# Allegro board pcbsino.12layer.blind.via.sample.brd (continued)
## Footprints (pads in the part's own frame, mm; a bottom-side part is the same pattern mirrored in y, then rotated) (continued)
0805
  rect 1.143x1.27 smd: 1(-0.889,0) 2(0.889,0)
1210
  rect 1.6x2.667 smd: 1(-1.397,0) 2(1.397,0)
FILT-NFM21PC
  rect 0.6x0.8 smd: 1(-1,0) 3(1,0)
  rect 0.6x1.3 smd: 2(0,0)
IND_IHLP1616AB
  rect 1.651x2.413 smd: 1(-1.651,0) 2(1.651,0)
LED_0603
  rect 0.889x0.813 smd: 1(-0.762,0) 2(0.762,0)
NFBGA_ZWS_169
  round 0.4 smd: A1(-4.8,4.8) A2(-4,4.8) A3(-3.2,4.8) A4(-2.4,4.8) A5(-1.6,4.8) A6(-0.8,4.8) A7(0,4.8) A8(0.8,4.8) A9(1.6,4.8) A10(2.4,4.8) A11(3.2,4.8) A12(4,4.8) A13(4.8,4.8) B1(-4.8,4) B2(-4,4) B3(-3.2,4) B4(-2.4,4) B5(-1.6,4) B6(-0.8,4) B7(0,4) B8(0.8,4) B9(1.6,4) B10(2.4,4) B11(3.2,4) B12(4,4) B13(4.8,4) C1(-4.8,3.2) C2(-4,3.2) C3(-3.2,3.2) C4(-2.4,3.2) C5(-1.6,3.2) C6(-0.8,3.2) C7(0,3.2) C8(0.8,3.2) C9(1.6,3.2) C10(2.4,3.2) C11(3.2,3.2) C12(4,3.2) C13(4.8,3.2) D1(-4.8,2.4) D2(-4,2.4) D3(-3.2,2.4) D4(-2.4,2.4) D5(-1.6,2.4) D6(-0.8,2.4) D7(0,2.4) D8(0.8,2.4) D9(1.6,2.4) D10(2.4,2.4) D11(3.2,2.4) D12(4,2.4) D13(4.8,2.4) E1(-4.8,1.6) E2(-4,1.6) E3(-3.2,1.6) E4(-2.4,1.6) E5(-1.6,1.6) E6(-0.8,1.6) E7(0,1.6) E8(0.8,1.6) E9(1.6,1.6) E10(2.4,1.6) E11(3.2,1.6) E12(4,1.6) E13(4.8,1.6) F1(-4.8,0.8) F2(-4,0.8) F3(-3.2,0.8) F4(-2.4,0.8) F5(-1.6,0.8) F6(-0.8,0.8) F7(0,0.8) F8(0.8,0.8) F9(1.6,0.8) F10(2.4,0.8) F11(3.2,0.8) F12(4,0.8) F13(4.8,0.8) G1(-4.8,0) G2(-4,0) G3(-3.2,0) G4(-2.4,0) G5(-1.6,0) G6(-0.8,0) G7(0,0) G8(0.8,0) G9(1.6,0) G10(2.4,0) G11(3.2,0) G12(4,0) G13(4.8,0) H1(-4.8,-0.8) H2(-4,-0.8) H3(-3.2,-0.8) H4(-2.4,-0.8) H5(-1.6,-0.8) H6(-0.8,-0.8) H7(0,-0.8) H8(0.8,-0.8) H9(1.6,-0.8) H10(2.4,-0.8) H11(3.2,-0.8) H12(4,-0.8) H13(4.8,-0.8) J1(-4.8,-1.6) J2(-4,-1.6) J3(-3.2,-1.6) J4(-2.4,-1.6) J5(-1.6,-1.6) J6(-0.8,-1.6) J7(0,-1.6) J8(0.8,-1.6) J9(1.6,-1.6) J10(2.4,-1.6) J11(3.2,-1.6) J12(4,-1.6) J13(4.8,-1.6) K1(-4.8,-2.4) K2(-4,-2.4) K3(-3.2,-2.4) K4(-2.4,-2.4) K5(-1.6,-2.4) K6(-0.8,-2.4) K7(0,-2.4) K8(0.8,-2.4) K9(1.6,-2.4) K10(2.4,-2.4) K11(3.2,-2.4) K12(4,-2.4) K13(4.8,-2.4) L1(-4.8,-3.2) L2(-4,-3.2) L3(-3.2,-3.2) L4(-2.4,-3.2) L5(-1.6,-3.2) L6(-0.8,-3.2) L7(0,-3.2) L8(0.8,-3.2) L9(1.6,-3.2) L10(2.4,-3.2) L11(3.2,-3.2) L12(4,-3.2) L13(4.8,-3.2) M1(-4.8,-4) M2(-4,-4) M3(-3.2,-4) M4(-2.4,-4) M5(-1.6,-4) M6(-0.8,-4) M7(0,-4) M8(0.8,-4) M9(1.6,-4) M10(2.4,-4) M11(3.2,-4) M12(4,-4) M13(4.8,-4) N1(-4.8,-4.8) N2(-4,-4.8) N3(-3.2,-4.8) N4(-2.4,-4.8) N5(-1.6,-4.8) N6(-0.8,-4.8) N7(0,-4.8) N8(0.8,-4.8) N9(1.6,-4.8) N10(2.4,-4.8) N11(3.2,-4.8) N12(4,-4.8) N13(4.8,-4.8)
PLLD1_27-20R
  round 1 hole 0.7: 1(-5.715,-0.635) 2(-5.715,0.635) 3(-4.445,-0.635) 4(-4.445,0.635) 5(-3.175,-0.635) 6(-3.175,0.635) 7(-1.905,-0.635) 8(-1.905,0.635) 9(-0.635,-0.635) 10(-0.635,0.635) 11(0.635,-0.635) 12(0.635,0.635) 13(1.905,-0.635) 14(1.905,0.635) 15(3.175,-0.635) 16(3.175,0.635) 17(4.445,-0.635) 18(4.445,0.635) 19(5.715,-0.635) 20(5.715,0.635)
QFN48
  oval 0.9x0.22 smd: 1(-2.95,2.2) 2(-2.95,1.8) 3(-2.95,1.4) 4(-2.95,1) 5(-2.95,0.6) 6(-2.95,0.2) 7(-2.95,-0.2) 8(-2.95,-0.6) 9(-2.95,-1) 10(-2.95,-1.4) 11(-2.95,-1.8) 12(-2.95,-2.2) 25(2.95,-2.2) 26(2.95,-1.8) 27(2.95,-1.4) 28(2.95,-1) 29(2.95,-0.6) 30(2.95,-0.2) 31(2.95,0.2) 32(2.95,0.6) 33(2.95,1) 34(2.95,1.4) 35(2.95,1.8) 36(2.95,2.2)
  oval 0.22x0.9 smd: 13(-2.2,-2.95) 14(-1.8,-2.95) 15(-1.4,-2.95) 16(-1,-2.95) 17(-0.6,-2.95) 18(-0.2,-2.95) 19(0.2,-2.95) 20(0.6,-2.95) 21(1,-2.95) 22(1.4,-2.95) 23(1.8,-2.95) 24(2.2,-2.95) 37(2.2,2.95) 38(1.8,2.95) 39(1.4,2.95) 40(1,2.95) 41(0.6,2.95) 42(0.2,2.95) 43(-0.2,2.95) 44(-0.6,2.95) 45(-1,2.95) 46(-1.4,2.95) 47(-1.8,2.95) 48(-2.2,2.95)
  rect 4.3x4.3 smd: 49(0,0)
RV-3129-C3
  rect 0.8x0.5 smd: 1(-1.15,1.6) 2(-1.15,0.8) 3(-1.15,0) 4(-1.15,-0.8) 5(-1.15,-1.6) 6(1.15,-1.6) 7(1.15,-0.8) 8(1.15,0) 9(1.15,0.8) 10(1.15,1.6)
SC-70-6
  rect 0.4x0.7 smd: 1(-0.65,-0.992) 2(0,-0.992) 3(0.65,-0.992) 4(0.65,0.992) 5(0,0.992) 6(-0.65,0.992)
SODIMM-204
  rect 0.45x2.5 smd: 1(0,0) 2(0,0) 3(0.6,0) 4(0.6,0) 5(1.2,0) 6(1.2,0) 7(1.8,0) 8(1.8,0) 9(2.4,0) 10(2.4,0) 11(3,0) 12(3,0) 13(3.6,0) 14(3.6,0) 15(4.2,0) 16(4.2,0) 17(4.8,0) 18(4.8,0) 19(5.4,0) 20(5.4,0) 21(6,0) 22(6,0) 23(6.6,0) 24(6.6,0) 25(7.2,0) 26(7.2,0) 27(7.8,0) 28(7.8,0) 29(8.4,0) 30(8.4,0) 31(9,0) 32(9,0) 33(9.6,0) 34(9.6,0) 35(10.2,0) 36(10.2,0) 37(10.8,0) 38(10.8,0) 39(11.4,0) 40(11.4,0) 41(12,0) 42(12,0) 43(12.6,0) 44(12.6,0) 45(13.2,0) 46(13.2,0) 47(13.8,0) 48(13.8,0) 49(14.4,0) 50(14.4,0) 51(15,0) 52(15,0) 53(15.6,0) 54(15.6,0) 55(16.2,0) 56(16.2,0) 57(16.8,0) 58(16.8,0) 59(17.4,0) 60(17.4,0) 61(18,0) 62(18,0) 63(18.6,0) 64(18.6,0) 65(19.2,0) 66(19.2,0) 67(19.8,0) 68(19.8,0) 69(20.4,0) 70(20.4,0) 71(21,0) 72(21,0) 73(24,0) 74(24,0) 75(24.6,0) 76(24.6,0) 77(25.2,0) 78(25.2,0) 79(25.8,0) 80(25.8,0) 81(26.4,0) 82(26.4,0) 83(27,0) 84(27,0) 85(27.6,0) 86(27.6,0) 87(28.2,0) 88(28.2,0) 89(28.8,0) 90(28.8,0) 91(29.4,0) 92(29.4,0) 93(30,0) 94(30,0) 95(30.6,0) 96(30.6,0) 97(31.2,0) 98(31.2,0) 99(31.8,0) 100(31.8,0) 101(32.4,0) 102(32.4,0) 103(33,0) 104(33,0) 105(33.6,0) 106(33.6,0) 107(34.2,0) 108(34.2,0) 109(34.8,0) 110(34.8,0) 111(35.4,0) 112(35.4,0) 113(36,0) 114(36,0) 115(36.6,0) 116(36.6,0) 117(37.2,0) 118(37.2,0) 119(37.8,0) 120(37.8,0) 121(38.4,0) 122(38.4,0) 123(39,0) 124(39,0) 125(39.6,0) 126(39.6,0) 127(40.2,0) 128(40.2,0) 129(40.8,0) 130(40.8,0) 131(41.4,0) 132(41.4,0) 133(42,0) 134(42,0) 135(42.6,0) 136(42.6,0) 137(43.2,0) 138(43.2,0) 139(43.8,0) 140(43.8,0) 141(44.4,0) 142(44.4,0) 143(45,0) 144(45,0) 145(45.6,0) 146(45.6,0) 147(46.2,0) 148(46.2,0) 149(46.8,0) 150(46.8,0) 151(47.4,0) 152(47.4,0) 153(48,0) 154(48,0) 155(48.6,0) 156(48.6,0) 157(49.2,0) 158(49.2,0) 159(49.8,0) 160(49.8,0) 161(50.4,0) 162(50.4,0) 163(51,0) 164(51,0) 165(51.6,0) 166(51.6,0) 167(52.2,0) 168(52.2,0) 169(52.8,0) 170(52.8,0) 171(53.4,0) 172(53.4,0) 173(54,0) 174(54,0) 175(54.6,0) 176(54.6,0) 177(55.2,0) 178(55.2,0) 179(55.8,0) 180(55.8,0) 181(56.4,0) 182(56.4,0) 183(57,0) 184(57,0) 185(57.6,0) 186(57.6,0) 187(58.2,0) 188(58.2,0) 189(58.8,0) 190(58.8,0) 191(59.4,0) 192(59.4,0) 193(60,0) 194(60,0) 195(60.6,0) 196(60.6,0) 197(61.2,0) 198(61.2,0) 199(61.8,0) 200(61.8,0) 201(62.4,0) 202(62.4,0) 203(63,0) 204(63,0)
SOT23
  rect 0.991x0.991 smd: 1(-0.965,-1.181) 2(0.965,-1.181)
  rect 0.991x1.2 smd: 3(0,1.081)
SOT23-3L
  rect 1.016x1.016 smd: 1(-1.016,-1.105) 2(1.016,-1.105) 3(0,1.105)
SOT323
  rect 0.5x0.6 smd: D(0,0.95) G(-0.65,-0.95) S(0.65,-0.95)
SOT-23-5
  rect 0.61x1.321 smd: 1(-0.95,-1.2) 2(0,-1.2) 3(0.95,-1.2) 4(0.95,1.2) 5(-0.95,1.2)
SOT-23-6
  rect 0.61x1.524 smd: 1(-0.95,-1.2) 2(0,-1.2) 3(0.95,-1.2) 4(0.95,1.2) 5(0,1.2) 6(-0.95,1.2)
SRN3015
  rect 2.7x1 smd: 1(0,1.1) 2(0,-1.1)
TP_SMD1MMCIRCLE
  round 1.021 smd: 1(0,0)
unnamed
  round 1.016 smd: 1(0,0)
XTAL4_3P2X2P5_SMD
  rect 1.397x1.143 smd: 1(-1.1,-0.8) 2(1.1,-0.8) 3(1.1,0.8) 4(-1.1,0.8)

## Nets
GND: C1.1 C2.2 C3.1 C4.2 C5.2 C6.2 C7.2 C8.1 C9.2 C10.2 C11.2 C12.2 C13.2 C14.2 C15.2 C16.2 C17.1 C18.2 C19.2 C20.2 C21.2 C22.2 C23.2 C24.2 C25.2 C26.2 C27.2 C28.2 C29.2 C30.2 C31.1 C32.2 C33.2 C34.2 C35.1 C36.1 C37.2 C38.2 C39.2 C40.1 C41.1 C42.2 C43.1 C44.1 C45.2 C46.1 C47.2 C48.1 C49.1 C50.1 C51.1 C52.2 C53.2 C54.2 C55.2 C56.2 C57.2 C58.2 C59.2 C60.2 C61.2 C62.2 C63.2 C64.2 C65.2 C69.2 C70.2 C71.2 C72.2 C76.2 C77.2 C78.2 C79.2 C80.2 C81.1 C82.1 C83.1 C84.1 C85.1 C86.2 C87.1 C88.1 C89.1 C90.1 C91.1 C92.2 C93.2 C94.2 C95.2 C96.2 C97.2 C98.2 C99.2 C100.2 C101.2 C102.2 C106.2 C107.2 C108.2 C109.2 C113.2 C114.2 C115.2 C116.2 C117.2 C118.1 C119.1 C120.1 C121.1 C122.1 C123.2 C124.1 C125.1 C126.1 C127.1 C128.1 C129.2 C130.2 C131.2 C132.2 C133.2 C134.2 C135.2 C136.2 C137.2 C138.2 C139.1 C140.1 C141.1 C142.1 C143.1 C144.2 C145.2 C146.1 C147.1 C148.1 C149.1 C150.1 C151.1 C152.2 C153.2 C154.2 C155.2 C156.2 C157.1 C158.2 C159.2 C160.2 C161.2 C162.2 C163.2 C164.2 C177.2 C178.1 C179.1 C180.2 C181.2 C182.2 C183.2 C184.2 C185.2 C186.2 C187.2 C188.2 C189.2 C190.2 C191.2 C192.2 C193.2 C194.2 C195.2 C196.2 C197.2 C198.2 C199.2 C200.2 C201.2 C202.2 C203.2 C204.2 C205.2 C206.2 C207.2 C208.2 C209.2 C210.2 C211.2 C212.2 C213.2 C214.2 C215.2 C216.2 C217.2 C218.2 C219.2 C220.2 C221.2 C222.2 C223.2 C224.2 C225.2 C226.2 C227.2 C228.2 C229.2 C230.2 C231.2 C232.2 C233.2 C234.2 C235.2 C236.2 C237.2 C238.2 C239.2 C240.2 C241.2 C242.2 C243.2 C244.2 C245.2 C246.2 C247.2 C248.2 C249.2 C250.2 C251.2 C252.2 C253.2 C254.2 C255.2 C256.2 C257.2 C258.2 C259.2 C260.2 C261.2 C262.2 C263.2 C264.2 C265.2 C266.2 C267.2 C268.2 C269.2 C270.2 C271.2 C272.2 C273.2 C274.2 C275.2 C276.2 C277.2 C278.2 C279.2 C280.2 C281.2 C282.2 C283.2 C284.2 C285.2 C286.2 C287.2 C288.2 C289.2 C290.2 C291.2 C292.2 C293.2 C294.2 C295.2 C296.2 C297.2 C298.2 C299.2 C300.2 C301.2 C302.2 C303.2 C304.2 C305.2 C306.2 C307.2 C308.2 C309.2 C310.2 C311.2 C312.2 C313.2 C314.2 C315.2 C316.2 C317.2 C318.2 C319.1 C320.2 C321.1 C322.2 C323.1 C324.2 C325.1 C326.2 C327.1 C328.2 C329.1 C330.2 C331.1 C332.2 C333.1 D1.1(C) L22.2(GND) L23.2(GND) L24.2(GND) MH1.1(TP) MH2.1(TP) MH3.1(TP) MH4.1(TP) MH5.1(TP) MH6.1(TP) P1.4(TDIS) P1.8(GND.1) P1.10(GND.2) P1.12(GND.3) P1.16(GND.4) P1.20(GND.5) Q3.S(SOURCE) Q4.S(SOURCE) Q5.S(SOURCE) Q6.S(SOURCE) Q7.S(SOURCE) Q8.S(SOURCE) R7.1 R22.1 R26.1 R29.2 R31.2 R34.2 R35.1 R37.1 R38.1 R39.1 R40.1 R42.1 R43.2 R46.2 R49.2 R52.2 R59.2 R60.2 R61.2 R62.2 R64.2 R95.2 R96.2 R97.2 R98.2 R99.1 R128.2 R129.2 R130.2 R131.2 R157.2 R158.2 R159.2 R160.1 R162.1 R183.2 R184.2 R191.2 R196.2 R198.2 R200.2 R202.2 R204.2 R206.2 R208.2 R214.2 R217.2 R219.2 R221.2 R223.2 R225.2 R231.2 R233.2 R236.2 R237.1 R238.1 R239.1 R272.1 R273.1 R274.1 R278.1 R280.1 R281.1 R282.1 R283.1 R285.1 R287.1 R301.1 R302.1 R303.1 R307.1 R309.1 R310.1 R311.1 R312.1 R314.1 R316.1 R318.2 R326.2 U1.2(GND) U2.4(PGND) U2.8(GND) U2.11(PWRPAD) U3.A1(SUB_GND_A1) U3.A4(REFGND1) U3.A7(GNDANA) U3.A13(SUB_GND_A13) U3.B2(GPADC_IN0) U3.B8(SYNC_TO_EXCLOCK) U3.B10(SUB_GND_B10) U3.B11(SUB_GND_B11) U3.C2(GPADC_IN1) U3.C3(GPADC_IN2) U3.C12(SMPS12_FBK_GND) U3.D4(SMPS7_GND_1) U3.D5(SMPS7_GND_2) U3.D6(SUB_GND_D6) U3.D7(SUB_GND_D7) U3.D10(SMPS1_GND_1) U3.E4(SMPS7_GND_3) U3.E7(VAC/ACOK) U3.E8(SUB_GND_E8) U3.E9(SMPS1_GND_2) U3.E10(SMPS1_GND_3) U3.F4(SMPS4_GND_1) U3.F5(AGND.1) U3.F6(SUB_GND_F6) U3.F7(SUB_GND_F7) U3.F9(SMPS2_GND_1) U3.F10(SMPS2_GND_2) U3.G4(SMPS4_GND_2) U3.G5(SMPS4_GND_3) U3.G7(SUB_GND_G7) U3.G10(SMPS2_GND_3) U3.H4(SMPS5_GND_1) U3.H5(SMPS5_GND_2) U3.H6(SUB_GND_H6) U3.H7(SUB_GND_H7) U3.H10(SMPS3_GND_1) U3.J4(SMPS5_GND_3) U3.J6(SUB_GND_J6) U3.J9(SMPS3_GND_2) U3.J10(SMPS3_GND_3) U3.K3(SMPS45_FDBK_GND) U3.L5(SMPS6_GND) U3.L6(SMPS6_GND_1) U3.L7(SMPS9_GND) U3.L8(SMPS9_GND_1) U3.L9(SMPS8_GND_1) U3.L10(SMPS8_GND) U3.M1(SUB_GND_M1) U3.M2(SUB_GND_M2) U3.M12(GND_DIG) U3.M13(AGND.2) U3.N1(SUB_GND_N1) U3.N2(VIO_GND) U3.N13(SUB_GND_N13) U4.3(GND) U5.3(GND) U6.A1(VSS.9) U6.A2(VSS.11) U6.A6(VSS.15) U6.A14(VSS.41) U6.A23(VSS.68) U6.A28(VSS.79) U6.AA8(VSS.17) U6.AA9(VSS.19) U6.AA10(VSS.14) U6.AA11(VSSA_USB.2) U6.AA14(VSS.48) U6.AA15(VSS.51) U6.AA20(VSS.61) U6.AB11(VSSA_USB.1) U6.AB14(VSS.40) U6.AB20(VSS.60) U6.AC14(VSSA_OSC1) U6.AD1(VSS.3) U6.AD10(VSSA_USB3) U6.AD13(VSSA_PCIE.1) U6.AD19(VSSA_HDMI.2) U6.AD24(VSS.70) U6.AE10(VSSA_SATA) U6.AE13(VSSA_PCIE.2) U6.AE19(VSSA_HDMI.1) U6.AF15(VSSA_OSC0) U6.AG1(VSS.2) U6.AH1(VSS.1) U6.AH2(VSS.10) U6.AH8(VSS.53) U6.AH20(VSS.52) U6.AH28(VSS.75) U6.B1(VSS.8) U6.D13(VSS.39) U6.D19(VSS.59) U6.E13(VSS.38) U6.E19(VSS.58) U6.F1(VSS.7) U6.F7(VSS.54) U6.G7(VSS.57) U6.G8(VSS.65) U6.G9(VSS.66) U6.H12(VSS.33) U6.J12(VSS.32) U6.J15(VSS.XX) U6.J28(VSS.78) U6.K1(VSS.6) U6.K4(VSS.12) U6.K5(VSS.13) U6.K15(VSS.28) U6.K24(VSS.55) U6.K25(VSS.56) U6.L13(VSS.37) U6.L14(VSS.46) U6.M19(VSS.69) U6.N14(VSS.X5) U6.N15(VSS.16) U6.N19(VSS.18) U6.N24(VSS.72) U6.N25(VSS.74) U6.P28(VSS.77) U6.R1(VSS.5) U6.R12(VSS.29) U6.R13(VSS.X6) U6.R15(VSS.43) U6.R21(VSS.64) U6.T10(VSS.21) U6.T11(VSS.26) U6.T12(VSS.23) U6.T14(VSS.X7) U6.T15(VSS.42) U6.T17(VSS.47) U6.T18(VSS.24) U6.T21(VSS.27) U6.U14(VSSA_VIDEO) U6.U15(VSS.X8) U6.U17(VSS.X9) U6.U20(VSS.62) U6.U21(VSS.63) U6.V15(VSS.30) U6.V17(VSS.X10) U6.W1(VSS.4) U6.W15(VSS.36) U6.W24(VSS.71) U6.W25(VSS.73) U6.W28(VSS.76) U7.3(GND) U8.A9(VSS.1) U8.B1(VSSQ.1) U8.B3(VSS.2) U8.B9(VSSQ.2) U8.D1(VSSQ.3) U8.D8(VSSQ.4) U8.E1(VSS.3) U8.E2(VSSQ.5) U8.E8(VSSQ.6) U8.F9(VSSQ.7) U8.G1(VSSQ.8) U8.G8(VSS.4) U8.G9(VSSQ.9) U8.J2(VSSDL) U8.J8(VSS.5) U8.M1(VSS.6) U8.M9(VSS.7) U8.P1(VSS.8) U8.P9(VSS.9) U8.T1(VSS.10) U8.T9(VSS.11) U9.A9(VSS.1) U9.B1(VSSQ.1) U9.B3(VSS.2) U9.B9(VSSQ.2) U9.D1(VSSQ.3) U9.D8(VSSQ.4) U9.E1(VSS.3) U9.E2(VSSQ.5) U9.E8(VSSQ.6) U9.F9(VSSQ.7) U9.G1(VSSQ.8) U9.G8(VSS.4) U9.G9(VSSQ.9) U9.J2(VSSDL) U9.J8(VSS.5) U9.M1(VSS.6) U9.M9(VSS.7) U9.P1(VSS.8) U9.P9(VSS.9) U9.T1(VSS.10) U9.T9(VSS.11) U10.A9(VSS.1) U10.B1(VSSQ.1) U10.B3(VSS.2) U10.B9(VSSQ.2) U10.D1(VSSQ.3) U10.D8(VSSQ.4) U10.E1(VSS.3) U10.E2(VSSQ.5) U10.E8(VSSQ.6) U10.F9(VSSQ.7) U10.G1(VSSQ.8) U10.G8(VSS.4) U10.G9(VSSQ.9) U10.J2(VSSDL) U10.J8(VSS.5) U10.M1(VSS.6) U10.M9(VSS.7) U10.P1(VSS.8) U10.P9(VSS.9) U10.T1(VSS.10) U10.T9(VSS.11) U11.A9(VSS.1) U11.B1(VSSQ.1) U11.B3(VSS.2) U11.B9(VSSQ.2) U11.D1(VSSQ.3) U11.D8(VSSQ.4) U11.E1(VSS.3) U11.E2(VSSQ.5) U11.E8(VSSQ.6) U11.F9(VSSQ.7) U11.G1(VSSQ.8) U11.G8(VSS.4) U11.G9(VSSQ.9) U11.J2(VSSDL) U11.J8(VSS.5) U11.M1(VSS.6) U11.M9(VSS.7) U11.P1(VSS.8) U11.P9(VSS.9) U11.T1(VSS.10) U11.T9(VSS.11) U12.A6(VSS1) U12.C4(VSSQ1) U12.E7(VSS2) U12.G5(VSS3) U12.H10(VSS4) U12.J5(VSS5) U12.K8(VSS6) U12.N2(VSSQ2) U12.N5(VSSQ3) U12.P4(VSSQ4) U12.P6(VSSQ5) U13.6(VSS) U14.2(GND) U15.4(GND) U16.4(VSS) U17.49(EGND) U18.3(GND) U19.49(EGND) U20.3(GND) XP1.1(GND17) XP1.19(GND18) XP1.37(GND19) XP1.55(GND20) XP1.71(GND21) XP1.87(GND) XP1.105(GND8) XP1.123(GND9) XP1.141(GND10) XP1.159(GND11) XP1.177(GND12) XP1.195(AUDIO_GND) Y1.2(NC0) Y1.4(NC1) Y2.2(NC0) Y2.4(NC1) Y3.2(NC0) Y3.4(NC1) Y4.2(NC0) Y4.4(NC1) Y5.2(NC0) Y5.4(NC1)
SODIMM_VIN5A_CLK0/VIN2B_HSYNC1: U6.AC5(EHRPWM2A) XP1.49(VIN5A_CLK0;GPIO6_10;I2C3_SDA;VI)
SODIMM_VIN5A_D0/VIN2B_D0: U6.AD6(MMC3_DAT5) XP1.163(VIN5A_D0;GPIO1_23;MMC3_DAT5;SPI)
SODIMM_VIN5A_D1/VIN2B_D1: U6.AC8(MMC3_DAT4) XP1.202(VIN5A_D1;PER_PWREN;GPIO1_22;MMC)
SODIMM_VIN5A_D2/VIN2B_D2: U6.AC3(MMC3_DAT3) XP1.52(VIN5A_D2;GPIO7_2;MMC3_DAT3;SPI3)
SODIMM_VIN5A_D3/VIN2B_D3: U6.AC9(MMC3_DAT2) XP1.58(VIN5A_D3;GPIO7_1;MMC3_DAT2;SPI3)
SODIMM_VIN5A_D4/VIN2B_D4: U6.AC6(MMC3_DAT1) XP1.65(VIN5A_D4;GPIO7_0;MMC3_DAT1;SPI3)
SODIMM_VIN5A_D5/VIN2B_D5: U6.AC7(MMC3_DAT0) XP1.63(VIN5A_D5;GPIO6_31;MMC3_DAT0;SPI)
SODIMM_VIN5A_D6/VIN2B_D6: U6.AC4(MMC3_CMD) XP1.69(VIN5A_D6;GPIO6_30;MMC3_CMD;SPI3)
SODIMM_VIN5A_D7/VIN2B_D7: U6.AD4(MMC3_CLK) XP1.75(VIN5A_D7;GPIO6_29;MMC3_CLK;VIN2)
SODIMM_VIN5A_DE0/VIN2B_VSYNC1: U6.AB4(GPIO6_11) XP1.43(VIN5A_DE0;GPIO6_11;I2C3_SCL;VIN)
SODIMM_VIN5A_HSYNC0/VIN2B_DE1: U6.AB8(MMC3_DAT6) XP1.194(VIN5A_HSYNC0;GPIO1_24;MMC3_DAT6)
SODIMM_VIN5A_VSYNC0/VIN2B_CLK1: U6.AB5(MMC3_DAT7) XP1.179(VIN5A_VSYNC0;GPIO1_25;MMC3_DAT7)
VDD_1V8: C41.2 C284.1 C285.1 C286.1 C287.1 C288.1 C289.1 C290.1 C291.1 C292.1 C293.1 C294.1 C295.1 D2.3(ANODE) D3.3(ANODE) Q1.3(COLLECTOR) Q2.3(COLLECTOR) R16.1 R17.1 TP20.1 U3.B6(LDO2_OUT) U6.AA7(VDDS_MLBP.1) U6.AA18(VDDS18V_DDR1.1) U6.AA19(VDDS18V_DDR1.2) U6.G18(VDDS18V.8) U6.H17(VDDS18V.11) U6.J21(VDDS18V_DDR2.3) U6.J22(VDDS18V_DDR2.4) U6.M8(VDDS18V.9) U6.M9(VDDS18V.7) U6.N8(VDDS18V.4) U6.N21(VDDS18V_DDR2.2) U6.P8(VDDS18V.5) U6.P20(VDDS18V_DDR2.5) U6.P21(VDDS18V_DDR2.1) U6.R8(VDDS18V.3) U6.T8(VDDS18V.2) U6.V21(VDDS18V.12) U6.V22(VDDS18V.6) U6.W17(VDDS18V.10) U6.W18(VDDS18V.1) U6.W21(VDDS18V_DDR1.4) U6.Y7(VDDS_MLBP.2) U6.Y21(VDDS18V_DDR1.3)
VDD_3V3: C2.1 C47.1 C53.1 C54.1 C61.1 C62.1 C140.2 C141.2 C142.2 C143.2 C144.1 C147.2 C148.2 C149.2 C150.2 C151.2 C152.1 C153.1 C154.1 C157.2 C158.1 C159.1 C196.1 C216.1 C307.1 C308.1 C309.1 C310.1 C311.1 C312.1 C313.1 C314.1 C315.1 C316.1 L9.2 L10.2 L11.2 L12.2 L16.2 L17.2 L18.2 P1.5(TVD) Q1.2(EMMITTER) R1.2 R5.2 R11.1 R13.2 R21.2 R33.1 R51.2 R53.1 R54.1 R55.2 R56.2 R57.2(P2) R58.2 R65.1 R66.2 R67.1 R142.1 R143.1 R144.1 R145.1 R146.1 R147.1 R148.1 R149.1 R150.1 R151.1 R152.1 R153.2 R154.1 R155.1 R156.1 R161.1 R167.1 R170.1 R182.1(P1) R185.1(P1) R190.1(P1) R193.2 R194.1(P1) R195.2 R197.1(P1) R199.1(P1) R201.1(P1) R203.1(P1) R205.1(P1) R207.1(P1) R212.1(P1) R216.1(P1) R218.1(P1) R220.1(P1) R222.1(P1) R224.1(P1) R226.2 R230.2 R232.2 R235.2 R244.1 R245.1 R246.2 R247.2 R275.1 R304.1 R323.2 R327.2 TP23.1 U2.10(VCC) U3.D9(VIO_IN) U3.J8(SMPS9_FBK) U5.5(VCC) U6.AB6(VDDSHV7.1) U6.AB7(VDDSHV7.2) U6.AD5(VDDSHV6.2) U6.AD7(VDDSHV6.4) U6.AE7(VDDSHV6.3) U6.AF5(VDDSHV6.1) U6.B6(VDDSHV2.1) U6.B23(VDDSHV3.9) U6.C24(VDDSHV4.1) U6.D10(VDDSHV2.5) U6.D16(VDDSHV3.4) U6.D22(VDDSHV3.8) U6.E3(VDDSHV1.1) U6.E5(VDDSHV1.4) U6.E10(VDDSHV2.4) U6.E16(VDDSHV3.3) U6.E22(VDDSHV3.7) U6.G4(VDDSHV1.2) U6.G5(VDDSHV1.3) U6.G15(VDDSHV3.2) U6.H8(VDDSHV1.5) U6.H9(VDDSHV1.6) U6.H10(VDDSHV2.2) U6.H11(VDDSHV2.3) U6.H15(VDDSHV3.1) U6.H16(VDDSHV3.6) U6.H18(VDDSHV3.5) U6.H19(VDDSHV3.10) U6.J8(VDDSHV11.2) U6.K8(VDDSHV11.1) U6.N4(VDDSHV10.2) U6.N5(VDDSHV10.4) U6.P10(VDDSHV10.6) U6.R7(VDDSHV10.5) U6.R10(VDDSHV10.7) U6.T4(VDDSHV10.1) U6.T5(VDDSHV10.3) U6.U10(VDDSHV9.3) U6.V12(VDDSHV5) U6.W4(VDDSHV9.1) U6.W5(VDDSHV9.2) U7.5(VCC) U12.C6(VCCQ1) U12.E6(VCC1) U12.F5(VCC2) U12.J10(VCC3) U12.K9(VCC4) U12.M4(VCCQ2) U12.N4(VCCQ3) U12.P3(VCCQ4) U12.P5(VCCQ5) U13.2(VDD) U14.1(VCCA) U15.8(VCC) U16.8(VCC) U18.5(VCC) U20.5(VCC)
VDD_CORE: C30.1 C217.1 C218.1 C219.1 C220.1 C221.1 C222.1 C223.1 C224.1 C225.1 C226.1 C227.1 C228.1 C229.1 C230.1 L7.2 TP14.1 U3.B1(SMPS7_FDBK) U6.H13(VDD.18) U6.H14(VDD.22) U6.J17(VDD.X1) U6.J18(VDD.X2) U6.L7(VDD.34) U6.L8(VDD.15) U6.N10(VDD.6) U6.N13(VDD.16) U6.P11(VDD.9) U6.P12(VDD.12) U6.P13(VDD.X3) U6.R11(VDD.8) U6.R16(VDD.26) U6.R19(VDD.27) U6.T13(VDD.13) U6.T16(VDD.25) U6.T19(VDD.X7) U6.U8(VDD.29) U6.U9(VDD.2) U6.U13(VDD.3) U6.U16(VDD.X8) U6.V8(VDD.1) U6.V16(VDD.X9)
VDD_DSP: C26.1 C28.1 C231.1 C232.1 C233.1 C234.1 C235.1 C236.1 C237.1 C238.1 C239.1 C240.1 L4.2 L5.2 TP11.1 U3.K2(SMPS45_FDBK) U6.J13(VDD_DSP.7) U6.K10(VDD_DSP.8) U6.K11(VDD_DSP.9) U6.K12(VDD_DSP.10) U6.K13(VDD_DSP.11) U6.L10(VDD_DSP.2) U6.L11(VDD_DSP.4) U6.L12(VDD_DSP.12) U6.M10(VDD_DSP.1) U6.M11(VDD_DSP.5) U6.M12(VDD_DSP.3) U6.M13(VDD_DSP.6)
VDD_GPU: C29.1 C246.1 C247.1 C248.1 C249.1 C250.1 C251.1 C252.1 C253.1 L6.2 TP13.1 U3.K6(SMPS6_FBK) U6.U11(VDD_GPU.5) U6.U12(VDD_GPU.6) U6.V10(VDD_GPU.2) U6.V11(VDD_GPU.3) U6.V14(VDD_GPU.7) U6.W10(VDD_GPU.1) U6.W11(VDD_GPU.4) U6.W13(VDD_GPU.8)
VDD_IVA: C39.1 C241.1 C242.1 C243.1 C244.1 C245.1 L8.2 TP18.1 U3.L11(SMPS8_FDBK) U6.U18(VDD_IVA.1[ECO]) U6.U19(VDD_IVA.2[ECO]) U6.V18(VDD_IVA.3[ECO]) U6.V19(VDD_IVA.4[ECO])
VDD_MPU: C19.1 C20.1 C254.1 C255.1 C256.1 C257.1 C258.1 C259.1 C260.1 C261.1 C262.1 C263.1 C264.1 C265.1 L1.2 L2.2 TP5.1 U3.B13(SMPS12_FBK) U6.K17(VDD_MPU.10) U6.K18(VDD_MPU.2) U6.L15(VDD_MPU.11) U6.L16(VDD_MPU.12) U6.L17(VDD_MPU.6) U6.L18(VDD_MPU.8) U6.L19(VDD_MPU.3) U6.M15(VDD_MPU.13) U6.M16(VDD_MPU.14) U6.M17(VDD_MPU.5) U6.M18(VDD_MPU.7) U6.N17(VDD_MPU.4) U6.N18(VDD_MPU.1) U6.P17(VDD_MPU.15) U6.P18(VDD_MPU.9) U6.R18(VDD_MPU.16)
VDD_RTC: C49.2 C63.1 TP24.1 U3.A5(LDO9_OUT) U6.AB15(VDD_RTC)
VDD_SD: C40.2 C317.1 C318.1 Q2.2(EMMITTER) R3.2 R6.2 TP19.1 U3.C6(LDO1_OUT) U6.W8(VDDSHV8.2) U6.Y8(VDDSHV8.1)
VDDA_1V8_PHY_LDO3: C43.2 L23.1(IN) TP21.1 U3.K11(LDO3_OUT)
VDDA_1V8_PHY_LDO3_F: C163.1 C164.1 C296.1 C297.1 L23.3(OUT) U6.AA13(VDDA_USB1) U6.AB12(VDDA_USB2) U6.V13(VDDA_SATA) U6.W12(VDDA_USB3)
VDDA_1V8_PHY_LDO4: C44.2 L24.1(IN) TP22.1 U3.K12(LDO4_OUT)
VDDA_1V8_PHY_LDO4_F: C303.1 C304.1 C305.1 C306.1 L24.3(OUT) U6.AA16(VDDA_PCIE1) U6.AA17(VDDA_PCIE0) U6.W14(VDDA_PCIE) U6.Y17(VDDA_HDMI)
VDDA_1V8_PLL: C51.2 C56.1 L22.1(IN) TP25.1 U3.B5(LDOLN_OUT) U6.AD16(VDDA_OSC.1) U6.AE16(VDDA_OSC.2)
VDDA_1V8_PLL_F: C298.1 C299.1 C300.1 C301.1 C302.1 L22.3(OUT) U6.M14(VDDA_ABE_PER) U6.N11(VDDA_DEBUG) U6.N12(VDDA_DSP) U6.N16(VDDA_MPU) U6.P14(VDDA_VIDEO) U6.P15(VDDA_GMAC_CORE) U6.P16(VDDA_DDR) U6.R14(VDDA_GPU) U6.R17(VDDA_IVA)
VDDS_DDR: C3.2 C8.2 C24.1 C66.2 C67.2 C68.2 C73.2 C74.1 C75.1 C80.1 C81.2 C82.2 C83.2 C84.2 C85.2 C86.1 C87.2 C88.2 C89.2 C90.2 C91.2 C92.1 C93.1 C94.1 C95.1 C96.1 C97.1 C98.1 C99.1 C100.1 C101.1 C103.2 C104.2 C105.2 C110.2 C111.1 C112.1 C117.1 C118.2 C119.2 C120.2 C121.2 C122.2 C123.1 C124.2 C125.2 C126.2 C127.2 C128.2 C129.1 C130.1 C131.1 C132.1 C133.1 C134.1 C135.1 C136.1 C137.1 C138.1 C266.1 C267.1 C268.1 C269.1 C270.1 C271.1 C272.1 C273.1 C274.1 C275.1 C276.1 C277.1 C278.1 C279.1 C280.1 C281.1 C282.1 C283.1 L3.2 R2.1 R100.1 TP8.1 U2.2(PVCC) U3.K13(SMPS3_FDBK) U6.AA21(VDDS_DDR1.4) U6.AA22(VDDS_DDR1.2) U6.AB21(VDDS_DDR1.3) U6.AB22(VDDS_DDR1.7) U6.AB24(VDDS_DDR1.10) U6.AB25(VDDS_DDR1.11) U6.AC22(VDDS_DDR1.6) U6.AD26(VDDS_DDR1.12) U6.AG20(VDDS_DDR1.9) U6.AG28(VDDS_DDR1.5) U6.AH27(VDDS_DDR1.13) U6.E24(VDDS_DDR2.9) U6.G22(VDDS_DDR2.5) U6.G23(VDDS_DDR2.6) U6.H20(VDDS_DDR2.1) U6.H21(VDDS_DDR2.11) U6.H22(VDDS_DDR2.4) U6.J27(VDDS_DDR2.12) U6.L20(VDDS_DDR2.8) U6.L21(VDDS_DDR2.3) U6.M20(VDDS_DDR2.13) U6.M21(VDDS_DDR2.2) U6.T24(VDDS_DDR2.7) U6.T25(VDDS_DDR2.10) U6.W16(VDDS_DDR1.1) U6.W27(VDDS_DDR1.8) U8.A1(VDDQ.1) U8.A8(VDDQ.2) U8.B2(VDD.1) U8.C1(VDDQ.3) U8.C9(VDDQ.4) U8.D2(VDDQ.5) U8.D9(VDD.2) U8.E9(VDDQ.6) U8.F1(VDDQ.7) U8.G7(VDD.3) U8.H2(VDDQ.8) U8.H9(VDDQ.9) U8.K2(VDDL) U8.K8(VDD.4) U8.N1(VDD.5) U8.N9(VDD.6) U8.R1(VDD.7) U8.R9(VDD.8) U9.A1(VDDQ.1) U9.A8(VDDQ.2) U9.B2(VDD.1) U9.C1(VDDQ.3) U9.C9(VDDQ.4) U9.D2(VDDQ.5) U9.D9(VDD.2) U9.E9(VDDQ.6) U9.F1(VDDQ.7) U9.G7(VDD.3) U9.H2(VDDQ.8) U9.H9(VDDQ.9) U9.K2(VDDL) U9.K8(VDD.4) U9.N1(VDD.5) U9.N9(VDD.6) U9.R1(VDD.7) U9.R9(VDD.8) U10.A1(VDDQ.1) U10.A8(VDDQ.2) U10.B2(VDD.1) U10.C1(VDDQ.3) U10.C9(VDDQ.4) U10.D2(VDDQ.5) U10.D9(VDD.2) U10.E9(VDDQ.6) U10.F1(VDDQ.7) U10.G7(VDD.3) U10.H2(VDDQ.8) U10.H9(VDDQ.9) U10.K2(VDDL) U10.K8(VDD.4) U10.N1(VDD.5) U10.N9(VDD.6) U10.R1(VDD.7) U10.R9(VDD.8) U11.A1(VDDQ.1) U11.A8(VDDQ.2) U11.B2(VDD.1) U11.C1(VDDQ.3) U11.C9(VDDQ.4) U11.D2(VDDQ.5) U11.D9(VDD.2) U11.E9(VDDQ.6) U11.F1(VDDQ.7) U11.G7(VDD.3) U11.H2(VDDQ.8) U11.H9(VDDQ.9) U11.K2(VDDL) U11.K8(VDD.4) U11.N1(VDD.5) U11.N9(VDD.6) U11.R1(VDD.7) U11.R9(VDD.8)
CLOCKOUT1: R322.1 U6.F21(TIMER3)
CLOCKOUT3: TP33.1 U6.C23(CLKOUT3)
DDR1_A0: R73.2(P2) U6.AD20(DDR1_A0) U8.N3(A0) U9.N3(A0)
DDR1_A1: R74.2(P2) U6.AC19(DDR1_A1) U8.P7(A1) U9.P7(A1)
DDR1_A2: R75.2(P2) U6.AC20(DDR1_A2) U8.P3(A2) U9.P3(A2)
DDR1_A3: R76.2(P2) U6.AB19(DDR1_A3) U8.N2(A3) U9.N2(A3)
DDR1_A4: R77.2(P2) U6.AF21(DDR1_A4) U8.P8(A4) U9.P8(A4)
DDR1_A5: R78.2(P2) U6.AH22(DDR1_A5) U8.P2(A5) U9.P2(A5)
DDR1_A6: R79.2(P2) U6.AG23(DDR1_A6) U8.R8(A6) U9.R8(A6)
DDR1_A7: R80.2(P2) U6.AE21(DDR1_A7) U8.R2(A7) U9.R2(A7)
DDR1_A8: R81.2(P2) U6.AF22(DDR1_A8) U8.T8(A8) U9.T8(A8)
DDR1_A9: R82.2(P2) U6.AE22(DDR1_A9) U8.R3(A9) U9.R3(A9)
DDR1_A10: R83.2(P2) U6.AD21(DDR1_A10) U8.L7(A10) U9.L7(A10)
DDR1_A11: R84.2(P2) U6.AD22(DDR1_A11) U8.R7(A11) U9.R7(A11)
DDR1_A12: R85.2(P2) U6.AC21(DDR1_A12) U8.N7(A12) U9.N7(A12)
DDR1_A13: R86.2(P2) U6.AF18(DDR1_A13) U8.T3(A13) U9.T3(A13)
DDR1_A14: R87.2(P2) U6.AE17(DDR1_A14) U8.T7(A14) U9.T7(A14)
DDR1_A15: R88.2(P2) U6.AD18(DDR1_A15) U8.M7(NC.M7/A15) U9.M7(NC.M7/A15)
DDR1_BA0: R89.2(P2) U6.AF17(DDR1_BA0) U8.M2(BA0) U9.M2(BA0)
DDR1_BA1: R90.2(P2) U6.AE18(DDR1_BA1) U8.N8(BA1) U9.N8(BA1)
DDR1_BA2: R91.2(P2) U6.AB18(DDR1_BA2) U8.M3(BA2) U9.M3(BA2)
DDR1_CASN: R71.2(P2) U6.AC18(DDR1_CASN) U8.K3(CAS#) U9.K3(CAS#)
DDR1_CKE: R68.2(P2) R98.1 U6.AG22(DDR1_CKE) U8.K9(CKE) U9.K9(CKE)
DDR1_CLK_N: R94.2(P2) U6.AH24(DDR1_NCK) U8.K7(CK#) U9.K7(CK#)
DDR1_CLK_P: R93.2(P2) U6.AG24(DDR1_CK) U8.J7(CK) U9.J7(CK)
DDR1_CSN0: R69.2(P2) U6.AH23(DDR1_CS0N) U8.L2(CS#) U9.L2(CS#)
DDR1_D0: U6.AF25(DDR1_D0) U8.H8(DQ5)
DDR1_D1: U6.AF26(DDR1_D1) U8.F7(DQ1)
DDR1_D2: U6.AG26(DDR1_D2) U8.F8(DQ3)
DDR1_D3: U6.AH26(DDR1_D3) U8.H3(DQ4)
DDR1_D4: U6.AF24(DDR1_D4) U8.E3(DQ0)
DDR1_D5: U6.AE24(DDR1_D5) U8.H7(DQ7)
DDR1_D6: U6.AF23(DDR1_D6) U8.F2(DQ2)
DDR1_D7: U6.AE23(DDR1_D7) U8.G2(DQ6)
DDR1_D8: U6.AC23(DDR1_D8) U8.A2(DQ13)
DDR1_D9: U6.AF27(DDR1_D9) U8.A7(DQ12)
DDR1_D10: U6.AG27(DDR1_D10) U8.C2(DQ11)
DDR1_D11: U6.AF28(DDR1_D11) U8.B8(DQ14)
DDR1_D12: U6.AE26(DDR1_D12) U8.C3(DQ9)
DDR1_D13: U6.AC25(DDR1_D13) U8.D7(DQ8)
DDR1_D14: U6.AC24(DDR1_D14) U8.C8(DQ10)
DDR1_D15: U6.AD25(DDR1_D15) U8.A3(DQ15)
DDR1_D16: U6.V20(DDR1_D16) U9.F8(DQ3)
DDR1_D17: U6.W20(DDR1_D17) U9.H8(DQ5)
DDR1_D18: U6.AB28(DDR1_D18) U9.E3(DQ0)
DDR1_D19: U6.AC28(DDR1_D19) U9.F2(DQ2)
DDR1_D20: U6.AC27(DDR1_D20) U9.H3(DQ4)
DDR1_D21: U6.Y19(DDR1_D21) U9.H7(DQ7)
DDR1_D22: U6.AB27(DDR1_D22) U9.G2(DQ6)
DDR1_D23: U6.Y20(DDR1_D23) U9.F7(DQ1)
DDR1_D24: U6.AA23(DDR1_D24) U9.A2(DQ13)
DDR1_D25: U6.Y22(DDR1_D25) U9.B8(DQ14)
DDR1_D26: U6.Y23(DDR1_D26) U9.C8(DQ10)
DDR1_D27: U6.AA24(DDR1_D27) U9.A3(DQ15)
DDR1_D28: U6.Y24(DDR1_D28) U9.A7(DQ12)
DDR1_D29: U6.AA26(DDR1_D29) U9.C2(DQ11)
DDR1_D30: U6.AA25(DDR1_D30) U9.C3(DQ9)
DDR1_D31: U6.AA28(DDR1_D31) U9.D7(DQ8)
DDR1_DQM0: U6.AD23(DDR1_DQM0) U8.E7(LDM)
DDR1_DQM1: U6.AB23(DDR1_DQM1) U8.D3(UDM)
DDR1_DQM2: U6.AC26(DDR1_DQM2) U9.E7(LDM)
DDR1_DQM3: U6.AA27(DDR1_DQM3) U9.D3(UDM)
DDR1_DQS0_N: U6.AG25(DDR1_DQSN0) U8.G3(LDQS#)
DDR1_DQS0_P: U6.AH25(DDR1_DQS0) U8.F3(LDQS)
DDR1_DQS1_N: U6.AE28(DDR1_DQSN1) U8.B7(UDQS#)
DDR1_DQS1_P: U6.AE27(DDR1_DQS1) U8.C7(UDQS)
DDR1_DQS2_N: U6.AD28(DDR1_DQSN2) U9.G3(LDQS#)
DDR1_DQS2_P: U6.AD27(DDR1_DQS2) U9.F3(LDQS)
DDR1_DQS3_N: U6.Y27(DDR1_DQSN3) U9.B7(UDQS#)
DDR1_DQS3_P: U6.Y28(DDR1_DQS3) U9.C7(UDQS)
DDR1_ODT0: R92.2(P2) U6.AE20(DDR1_ODT0) U8.K1(ODT) U9.K1(ODT)
DDR1_RASN: R70.2(P2) U6.AF20(DDR1_RASN) U8.J3(RAS#) U9.J3(RAS#)
DDR1_RST: R95.1 U6.AG21(DDR1_RST) U8.T2(RSTN) U9.T2(RSTN)
DDR1_WEN: R72.2(P2) U6.AH21(DDR1_WEN) U8.L3(WE#) U9.L3(WE#)
DDR2_A0: R106.2(P2) U6.R25(DDR2_A0) U10.N3(A0) U11.N3(A0)
DDR2_A1: R107.2(P2) U6.R26(DDR2_A1) U10.P7(A1) U11.P7(A1)
DDR2_A2: R108.2(P2) U6.R28(DDR2_A2) U10.P3(A2) U11.P3(A2)
DDR2_A3: R109.2(P2) U6.R27(DDR2_A3) U10.N2(A3) U11.N2(A3)
DDR2_A4: R110.2(P2) U6.P23(DDR2_A4) U10.P8(A4) U11.P8(A4)
DDR2_A5: R111.2(P2) U6.P22(DDR2_A5) U10.P2(A5) U11.P2(A5)
DDR2_A6: R112.2(P2) U6.P25(DDR2_A6) U10.R8(A6) U11.R8(A6)
DDR2_A7: R113.2(P2) U6.N20(DDR2_A7) U10.R2(A7) U11.R2(A7)
DDR2_A8: R114.2(P2) U6.P27(DDR2_A8) U10.T8(A8) U11.T8(A8)
DDR2_A9: R115.2(P2) U6.N27(DDR2_A9) U10.R3(A9) U11.R3(A9)
DDR2_A10: R116.2(P2) U6.N23(DDR2_A10) U10.L7(A10) U11.L7(A10)
DDR2_A11: R117.2(P2) U6.P26(DDR2_A11) U10.R7(A11) U11.R7(A11)
DDR2_A12: R118.2(P2) U6.N28(DDR2_A12) U10.N7(A12) U11.N7(A12)
DDR2_A13: R119.2(P2) U6.T22(DDR2_A13) U10.T3(A13) U11.T3(A13)
DDR2_A14: R120.2(P2) U6.R22(DDR2_A14) U10.T7(A14) U11.T7(A14)
DDR2_A15: R121.2(P2) U6.U22(DDR2_A15) U10.M7(NC.M7/A15) U11.M7(NC.M7/A15)
DDR2_BA0: R122.2(P2) U6.U23(DDR2_BA0) U10.M2(BA0) U11.M2(BA0)
DDR2_BA1: R123.2(P2) U6.U27(DDR2_BA1) U10.N8(BA1) U11.N8(BA1)
DDR2_BA2: R124.2(P2) U6.U26(DDR2_BA2) U10.M3(BA2) U11.M3(BA2)
DDR2_CASN: R104.2(P2) U6.U28(DDR2_CASN) U10.K3(CAS#) U11.K3(CAS#)
DDR2_CKE: R101.2(P2) R131.1 U6.U24(DDR2_CKE) U10.K9(CKE) U11.K9(CKE)
DDR2_CLK_N: R127.2(P2) U6.T27(DDR2_NCK) U10.K7(CK#) U11.K7(CK#)
DDR2_CLK_P: R126.2(P2) U6.T28(DDR2_CK) U10.J7(CK) U11.J7(CK)
DDR2_CSN0: R102.2(P2) U6.P24(DDR2_CSN0) U10.L2(CS#) U11.L2(CS#)
DDR2_D0: U6.E26(DDR2_D0) U10.D7(DQ8)
DDR2_D1: U6.G25(DDR2_D1) U10.C2(DQ11)
DDR2_D2: U6.F25(DDR2_D2) U10.A3(DQ15)
DDR2_D3: U6.F24(DDR2_D3) U10.B8(DQ14)
DDR2_D4: U6.F26(DDR2_D4) U10.A2(DQ13)
DDR2_D5: U6.F27(DDR2_D5) U10.C3(DQ9)
DDR2_D6: U6.E27(DDR2_D6) U10.A7(DQ12)
DDR2_D7: U6.E28(DDR2_D7) U10.C8(DQ10)
DDR2_D8: U6.H23(DDR2_D8) U10.F8(DQ3)
DDR2_D9: U6.H25(DDR2_D9) U10.F7(DQ1)
DDR2_D10: U6.H24(DDR2_D10) U10.H8(DQ5)
DDR2_D11: U6.H26(DDR2_D11) U10.G2(DQ6)
DDR2_D12: U6.G26(DDR2_D12) U10.H7(DQ7)
DDR2_D13: U6.J25(DDR2_D13) U10.F2(DQ2)
DDR2_D14: U6.J26(DDR2_D14) U10.E3(DQ0)
DDR2_D15: U6.J24(DDR2_D15) U10.H3(DQ4)
DDR2_D16: U6.L22(DDR2_D16) U11.C2(DQ11)
DDR2_D17: U6.K20(DDR2_D17) U11.C8(DQ10)
DDR2_D18: U6.K21(DDR2_D18) U11.D7(DQ8)
DDR2_D19: U6.L23(DDR2_D19) U11.A2(DQ13)
DDR2_D20: U6.L24(DDR2_D20) U11.C3(DQ9)
DDR2_D21: U6.J23(DDR2_D21) U11.A7(DQ12)
DDR2_D22: U6.K22(DDR2_D22) U11.A3(DQ15)
DDR2_D23: U6.J20(DDR2_D23) U11.B8(DQ14)
DDR2_D24: U6.L27(DDR2_D24) U11.F7(DQ1)
DDR2_D25: U6.L26(DDR2_D25) U11.H8(DQ5)
DDR2_D26: U6.L25(DDR2_D26) U11.F8(DQ3)
DDR2_D27: U6.L28(DDR2_D27) U11.H7(DQ7)
DDR2_D28: U6.M23(DDR2_D28) U11.H3(DQ4)
DDR2_D29: U6.M24(DDR2_D29) U11.G2(DQ6)
DDR2_D30: U6.M25(DDR2_D30) U11.F2(DQ2)
DDR2_D31: U6.M26(DDR2_D31) U11.E3(DQ0)
DDR2_DQM0: U6.F28(DDR2_DQM0) U10.D3(UDM)
DDR2_DQM1: U6.G24(DDR2_DQM1) U10.E7(LDM)
DDR2_DQM2: U6.K23(DDR2_DQM2) U11.D3(UDM)
DDR2_DQM3: U6.M22(DDR2_DQM3) U11.E7(LDM)
DDR2_DQS0_N: U6.G27(DDR2_DQSN0) U10.B7(UDQS#)
DDR2_DQS0_P: U6.G28(DDR2_DQS0) U10.C7(UDQS)
DDR2_DQS1_N: U6.H28(DDR2_DQSN1) U10.G3(LDQS#)
DDR2_DQS1_P: U6.H27(DDR2_DQS1) U10.F3(LDQS)
DDR2_DQS2_N: U6.K28(DDR2_DQSN2) U11.B7(UDQS#)
DDR2_DQS2_P: U6.K27(DDR2_DQS2) U11.C7(UDQS)
DDR2_DQS3_N: U6.M27(DDR2_DQSN3) U11.G3(LDQS#)
DDR2_DQS3_P: U6.M28(DDR2_DQS3) U11.F3(LDQS)
DDR2_ODT0: R125.2(P2) U6.R23(DDR2_ODT0) U10.K1(ODT) U11.K1(ODT)
DDR2_RASN: R103.2(P2) U6.T23(DDR2_RASN) U10.J3(RAS#) U11.J3(RAS#)
DDR2_RST: R128.1 U6.R24(DDR2_RST) U10.T2(RSTN) U11.T2(RSTN)
DDR2_WEN: R105.2(P2) U6.U25(DDR2_WEN) U10.L3(WE#) U11.L3(WE#)
DDR_VREF_OFFN: R14.2(P2) U6.A22(GPIO7_11)
EEPROM_A0(NC): R226.1 R231.1 U16.1(NC.1)
EEPROM_A1(NC): R232.1 R233.1 U16.2(NC.2)
EEPROM_A2: R235.1 R236.1 U16.3(A2)
EMAC[0]_RXC/PHYAD1: C177.1 R260.2 R285.2 R286.1 U17.28(RXC/PHYAD1)
EMAC[0]_RXCTL/PHYAD2: R266.2 R287.2 R288.1 U17.27(RXCTL/PHYAD2)
EMAC[0]_RXD0/RXDLY: R267.2 R278.2 R279.1 U17.26(RXD0/RXDLY)
EMAC[0]_RXD1/CFG_MODE0: R261.2 R280.2 U17.25(RXD1/CFG_MODE0)
EMAC[0]_RXD2/CFG_MODE1: R262.2 R281.2 U17.24(RXD2/CFG_MODE1)
EMAC[0]_RXD3/CFG_MODE2: R263.2 R282.2 U17.23(RXD3/CFG_MODE2)
EMAC[0]_TXC: R268.1 U6.W9(EMAC(0)_TXC)
EMAC[0]_TXCTL: R264.1 U6.V9(EMAC(0)_TXCTL)
EMAC[0]_TXD0: R265.1 U6.U6(EMAC(0)_TXD0)
EMAC[0]_TXD1: R269.1 U6.V6(EMAC(0)_TXD1)
EMAC[0]_TXD2: R270.1 U6.U7(EMAC(0)_TXD2)
EMAC[0]_TXD3: R271.1 U6.V7(EMAC(0)_TXD3)
EMAC[1]_RXC/PHYAD1: C197.1 R290.2 R314.2 R315.1 U19.28(RXC/PHYAD1)
EMAC[1]_RXCTL/PHYAD2: R289.2 R316.2 R317.1 U19.27(RXCTL/PHYAD2)
EMAC[1]_RXD0/RXDLY: R291.2 R307.2 R308.1 U19.26(RXD0/RXDLY)
EMAC[1]_RXD1/CFG_MODE0: R292.2 R309.2 U19.25(RXD1/CFG_MODE0)
EMAC[1]_RXD2/CFG_MODE1: R293.2 R310.2 U19.24(RXD2/CFG_MODE1)
EMAC[1]_RXD3/CFG_MODE2: R294.2 R311.2 U19.23(RXD3/CFG_MODE2)
EMAC[1]_TXC: R297.1 U6.D5(EMAC(1)_TXC)
EMAC[1]_TXCTL: R296.1 U6.C2(EMAC(1)_TXCTL)
EMAC[1]_TXD0: R295.1 U6.D6(EMAC(1)_TXD0)
EMAC[1]_TXD1: R298.1 U6.B2(EMAC(1)_TXD1)
EMAC[1]_TXD2: R299.1 U6.C4(EMAC(1)_TXD2)
EMAC[1]_TXD3: R300.1 U6.C3(EMAC(1)_TXD3)
EMMC_NAND__MMC2_CLK: R135.1 U6.J7(MMC2_CLK)
EMMC_NAND__MMC2_CMD: R132.1 U6.H6(MMC2_CMD)
EMMC_NAND__MMC2_DAT0: R136.1 U6.J4(MMC2_DAT0)
EMMC_NAND__MMC2_DAT1: R133.1 U6.J6(MMC2_DAT1)
EMMC_NAND__MMC2_DAT2: R137.1 U6.H4(MMC2_DAT2)
EMMC_NAND__MMC2_DAT3: R138.1 U6.H5(MMC2_DAT3)
EMMC_NAND__MMC2_DAT4: R139.1 U6.K7(MMC2_DAT4)
EMMC_NAND__MMC2_DAT5: R140.1 U6.M7(MMC2_DAT5)
EMMC_NAND__MMC2_DAT6: R134.1 U6.J5(MMC2_DAT6)
EMMC_NAND__MMC2_DAT7: R141.1 U6.K6(MMC2_DAT7)
EMMC_NAND_MMC2_CLK: R135.2 R142.2 U12.M6(CLK)
EMMC_NAND_MMC2_CMD: R132.2 R143.2 U12.M5(CMD)
EMMC_NAND_MMC2_DAT0: R136.2 R144.2 U12.A3(DAT0)
EMMC_NAND_MMC2_DAT1: R133.2 R145.2 U12.A4(DAT1)
EMMC_NAND_MMC2_DAT2: R137.2 R146.2 U12.A5(DAT2)
EMMC_NAND_MMC2_DAT3: R138.2 R147.2 U12.B2(DAT3)
EMMC_NAND_MMC2_DAT4: R139.2 R148.2 U12.B3(DAT4)
EMMC_NAND_MMC2_DAT5: R140.2 R149.2 U12.B4(DAT5)
EMMC_NAND_MMC2_DAT6: R134.2 R150.2 U12.B5(DAT6)
EMMC_NAND_MMC2_DAT7: R141.2 R151.2 U12.B6(DAT7)
EMU0: P1.13(EMU0) R154.2 U6.G21(EMU0)
EMU1: P1.14(EMU1) R167.2 U6.D24(EMU1)
EMU_RSTN: C156.1 P1.15(SRST) R57.1(P1) U5.2(B)
ETH0_AND_RESETN: R276.2 U17.13(PHYRSTB) U18.4(Y)
ETH0_AVDD10: C189.1 C190.1 C192.1 C193.1 L14.1 U17.4(AVDD10 4) U17.9(AVDD10 9) U17.47(AVDD10 47)
ETH0_AVDD33: C178.2 C179.2 C180.1 L10.1 U17.1(AVDD33 1) U17.12(AVDD33 12)
ETH0_DVDD10: C194.1 C195.1 L15.1 U17.22(DVDD10 22)
ETH0_DVDD33: C181.1 C182.1 C183.1 L11.1 R259.2 R276.1 R277.1 R279.2 R284.2 R286.2 R288.2 U17.29(DVDD_RG) U17.30(DVDD33 30)
ETH0_INTN: R277.2 U6.B13(GPIO5_12) U17.34(INTB/PMEB/GPIO1)
ETH0_LED0/PHYAD0: R283.2 R284.1 U17.35(LED0/PHYAD0)
ETH0_RESETN: R275.2 U6.U3(GPIO3_17) U18.1(A)
ETH0_RSET: R272.2 U17.48(RSET)
ETH0_VDD10: C186.1 C187.1 L13.2 L14.2 L15.2
ETH0_VDDREG33: C184.1 C185.1 L12.1 U17.31(VDDREG)
ETH0_XTAL_IN: C188.1 U17.45(XTAL_IN) Y4.3
ETH0_XTAL_OUT: C191.1 U17.46(XTAL_OUT/EXT_CLK) Y4.1
ETH1_AND_RESETN: R305.2 U19.13(PHYRSTB) U20.4(Y)
ETH1_AVDD10: C210.1 C211.1 C212.1 C213.1 L20.1 U19.4(AVDD10 4) U19.9(AVDD10 9) U19.47(AVDD10 47)
ETH1_AVDD33: C198.1 C199.1 C200.1 L16.1 U19.1(AVDD33 1) U19.12(AVDD33 12)
ETH1_DVDD10: C214.1 C215.1 L21.1 U19.22(DVDD10 22)
ETH1_DVDD33: C201.1 C202.1 C203.1 L17.1 R305.1 R306.1 R308.2 R313.2 R315.2 R317.2 U19.29(DVDD_RG) U19.30(DVDD33 30)
ETH1_INTN: R306.2 U6.A11(GPIO5_11) U19.34(INTB/PMEB/GPIO1)
ETH1_LED0/PHYAD0: R312.2 R313.1 U19.35(LED0/PHYAD0)
ETH1_RESETN: R304.2 U6.B12(GPIO5_10) U20.1(A)
ETH1_RSET: R301.2 U19.48(RSET)
ETH1_VDD10: C206.1 C208.1 L19.2 L20.2 L21.2
ETH1_VDDREG33: C204.1 C205.1 L18.1 U19.31(VDDREG)
ETH1_XTAL_IN: C207.1 U19.45(XTAL_IN) Y5.3
ETH1_XTAL_OUT: C209.1 U19.46(XTAL_OUT/EXT_CLK) Y5.1
GPIO1_4: TP30.1 U6.D15(MCASP2_AXR4)
GPIO2_29: TP32.1 U6.B17(MCASP2_AXR6)
GPIO5_5: TP28.1 U6.J11(GPIO5_5)
GPIO5_6: TP29.1 U6.E12(GPIO5_6)
GPIO6_7: TP31.1 U6.B16(MCASP2_AXR5)
I2C1_SCL: R245.2 U3.L1(I2C1_SCL_SCK) U6.C20(I2C1_SCL)
I2C1_SDA: R244.2 U3.L2(I2C1_SDA_SDI) U6.C21(I2C1_SDA)
I2C3_SCL: TP34.1 U6.D14(I2C3_SCL)
I2C3_SDA: TP35.1 U6.C14(I2C3_SDA)
I2C4_SCL: R247.1 U3.M3(I2C2_SCL_SCE) U6.J14(I2C4_SCL) U13.4(SCL) U16.6(SCL)
I2C4_SDA: R246.1 U3.H8(I2C2_SDA_SDO) U6.B14(I2C4_SDA) U13.5(SDA) U16.5(SDA)
LDO_VRTC: C36.2 C65.1 C155.1 R20.2 R24.1 R28.1(P1) R30.2 R32.2 R41.1 R49.1 TP15.1 U3.A8(LDOVRTC_OUT) U6.AB13(VDDA_RTC) U14.6(VCCB)
LJCB_CLK_N: C175.2 R252.1 U6.AH15(LJCB_CLKN)
LJCB_CLK_P: C176.2 R252.2 U6.AG15(LJCB_CLKP)
MDIO_DATA: R259.1 U6.U4(MDIO_DATA) U17.15(MDIO) U19.15(MDIO)
MDIO_MCLK: U6.V1(MDIO_MCLK) U17.14(MDC) U19.14(MDC)
OSC0_XI: C58.1 U6.AE15(XI_OSC0) Y2.1
OSC0_XO: C57.1 U6.AD15(X0_OSC0) Y2.3
OSC1_XI: R62.1 U6.AC15(XI_OSC1) Y3.1
OSC1_XO: C60.1 U6.AC13(XO_OSC1) Y3.3
PCIE_TX0_N: C169.1 U6.AG14(PCIE_TXN0)
PCIE_TX0_P: C168.1 U6.AH14(PCIE_TXP0)
PCIE_TX1_N: C174.1 U6.AG12(PCIE_TXN1)
PCIE_TX1_P: C172.1 U6.AH12(PCIE_TXP1)
PMIC_INT: R58.1 R172.2 U3.K1(INT) U6.AD17(WAKEUP0)
PMIC_OFF: R19.1 R53.2 U6.Y11(ON_OFF)
PMIC_RESET_IN: R28.2(P2) U1.1(R\E\S\E\T\) U3.K9(RESET_IN)
PMIC_RESET_OUT: R65.2 U3.G6(RESET_OUT) U7.2(A)
PMIC_SMPS_POWERGOOD: Q3.G(GATE) R20.1 R21.1 U3.J7(POWERGOOD)
PMIC_VBUS_DET: R33.2 U4.4(Y) U6.AD2(GPIO3_26)
PORZ: C64.1 R66.1 R67.2 U6.AB17(RTC_PORZ) U6.AF14(RTC_ISO) U6.F22(PORZ) U7.4(Y) U18.2(B) U20.2(B)
QSPI_FLASH_QSPI1_CS0: R188.1 U6.P2(GPIO2_20)
QSPI_FLASH_QSPI1_D0: R179.1 U6.U1(GPIO2_6)
QSPI_FLASH_QSPI1_D1: R180.1 U6.P3(GPIO2_17)
QSPI_FLASH_QSPI1_D2: R178.1 U6.U2(GPIO2_5)
QSPI_FLASH_QSPI1_D3: R177.1 U6.T2(GPIO2_4)
QSPI_FLASH_QSPI1_RTCLK: R176.1 U6.R3(GPIO2_3)
QSPI_FLASH_QSPI1_SCLK: R181.1 U6.R2(GPIO2_8)
R__QSPI_FLASH_QSPI1_RTCLK: R176.2 R187.2
R__QSPI_FLASH_QSPI1_SCLK: R181.2 R186.1 R187.1
R_EMAC[0]_RXC: R260.1 U6.U5(EMAC(0)_RXC)
R_EMAC[0]_RXCTL: R266.1 U6.V5(EMAC(0)_RXCTL)
R_EMAC[0]_RXD0: R267.1 U6.W2(EMAC(0)_RXD0)
R_EMAC[0]_RXD1: R261.1 U6.Y2(EMAC(0)_RXD1)
R_EMAC[0]_RXD2: R262.1 U6.V3(EMAC(0)_RXD2)
R_EMAC[0]_RXD3: R263.1 U6.V4(EMAC(0)_RXD3)
R_EMAC[0]_TXC: R268.2 U17.21(TXC)
R_EMAC[0]_TXCTL: R264.2 U17.20(TXCTL)
R_EMAC[0]_TXD0: R265.2 U17.19(TXD0)
R_EMAC[0]_TXD1: R269.2 U17.18(TXD1)
R_EMAC[0]_TXD2: R270.2 U17.17(TXD2)
R_EMAC[0]_TXD3: R271.2 U17.16(TXD3)
R_EMAC[1]_RXC: R290.1 U6.C5(EMAC(1)_RXC)
R_EMAC[1]_RXCTL: R289.1 U6.A3(EMAC(1)_RXCTL)
R_EMAC[1]_RXD0: R291.1 U6.A4(EMAC(1)_RXD0)
R_EMAC[1]_RXD1: R292.1 U6.B5(EMAC(1)_RXD1)
R_EMAC[1]_RXD2: R293.1 U6.B4(EMAC(1)_RXD2)
R_EMAC[1]_RXD3: R294.1 U6.B3(EMAC(1)_RXD3)
R_EMAC[1]_TXC: R297.2 U19.21(TXC)
R_EMAC[1]_TXCTL: R296.2 U19.20(TXCTL)
R_EMAC[1]_TXD0: R295.2 U19.19(TXD0)
R_EMAC[1]_TXD1: R298.2 U19.18(TXD1)
R_EMAC[1]_TXD2: R299.2 U19.17(TXD2)
R_EMAC[1]_TXD3: R300.2 U19.16(TXD3)
R_QSPI_FLASH_QSPI1_CS0: R188.2 U15.1(CE#)
R_QSPI_FLASH_QSPI1_D0: R179.2 U15.5(SI(IO0))
R_QSPI_FLASH_QSPI1_D1: R180.2 U15.2(SO(IO1))
R_QSPI_FLASH_QSPI1_D2: R178.2 R189.1 R193.1 U15.3(WP#(IO2))
R_QSPI_FLASH_QSPI1_D3: R177.2 R192.1 R195.1 U15.7(HOLD# OR RESET# (IO3))
R_QSPI_FLASH_QSPI1_SCLK: R186.2 U15.6(SCK)
RSTOUTN: R25.1 R51.1 R52.1 R152.2 R192.2 R321.1 U6.F23(RSTOUTN) U12.K5(RST_N)
RTC_CLKOE: R153.1 R157.1 U6.A12(GPIO4_17) U13.1(CLKOE)
RTC_CLKOUT_1V8: R18.1 R63.1 R163.1
RTC_CLKOUT_3V3: R165.2 U14.3(A)
RTC_CLKOUT_3V3_R: R165.1 U13.3(CLKOUT)
RTC_INT: R61.1 R164.2 U6.AC16(WAKEUP3) U13.7(I\N\T\)
RTCK: P1.9(TCKRTN) R169.2
RTCKR: R169.1 U6.E18(RTCK)
SATA1_RX0_N: C171.2 U6.AH9(SATA1_RXN0)
SATA1_RX0_P: C173.2 U6.AG9(SATA1_RXP0)
SATA1_TX0_N: C167.2 U6.AG10(SATA1_TXN0)
SATA1_TX0_P: C170.2 U6.AH10(SATA1_TXP0)
SMPS1_SW: L1.1 U3.E11(SMPS1_SW_1) U3.E12(SMPS1_SW_2) U3.E13(SMPS1_SW_3)
SMPS2_SW: L2.1 U3.F11(SMPS2_SW_1) U3.F12(SMPS2_SW_2) U3.F13(SMPS2_SW_3)
SMPS3_SW: L3.1 U3.J11(SMPS3_SW_1) U3.J12(SMPS3_SW_2) U3.J13(SMPS3_SW_3)
SMPS4_SW: L4.1 U3.G1(SMPS4_SW_1) U3.G2(SMPS4_SW_2) U3.G3(SMPS4_SW_3)
SMPS5_SW: L5.1 U3.H1(SMPS5_SW_1) U3.H2(SMPS5_SW_2) U3.H3(SMPS5_SW_3)
SMPS6_SW: L6.1 U3.M5(SMPS6_SW_1) U3.N5(SMPS6_SW)
SMPS7_SW: L7.1 U3.D1(SMPS7_SW_1) U3.D2(SMPS7_SW_2) U3.D3(SMPS7_SW_3)
SMPS8_SW: L8.1 U3.M10(SMPS8_SW) U3.N10(SMPS8_SW_1)
SMPS9_SW: L9.1 U3.M7(SMPS9_SW) U3.N7(SMPS9_SW_1)
SODIMM__CLKOUT2/GPIO6_17: R209.1 U6.D18(CLKOOUT2)
SODIMM__GPIO6_19: R173.1 U6.B26(GPIO6_19)
SODIMM__SPI1_CS0: R258.1 U6.A24(GPIO7_10)
SODIMM__SPI1_D0: R255.1 U6.B25(GPIO7_9)
SODIMM__SPI1_D1: R254.1 U6.F16(GPIO7_8)
SODIMM__SPI1_SCLK: R253.1 U6.A25(GPIO7_7)
SODIMM__UART1_RXD: R250.1 U6.B27(UART1_RXD)
SODIMM__UART1_TXD: R251.1 U6.C26(UART1_TXD)
SODIMM__UART2_RXD: R256.1 U6.D28(GPIO7_26)
SODIMM__UART2_TXD: R257.1 U6.D26(GPIO7_27)
SODIMM__UART3_RXD: R240.1 U6.V2(UART3_RXD)
SODIMM__UART3_TXD: R241.1 U6.Y1(UART3_TXD)
SODIMM__UART5_RXD: R213.1 U6.B19(MCASP3_AXR0)
SODIMM__UART5_TXD: R215.1 U6.C17(MCASP3_AXR1)
SODIMM__UART6_RXD: R243.1 U6.G12(I2C5_SDA)
SODIMM__UART6_TXD: R242.1 U6.F12(I2C5_SCL)
SODIMM__UART7_RXD/GPIO5_13: R211.1 U6.B18(MCASP3_ACLKX)
SODIMM__UART7_TXD/GPIO5_14: R210.1 U6.F15(MCASP3_FSX)
SODIMM__UART8_RXD: R249.1 U6.G20(DCAN1_TX)
SODIMM__UART8_TXD: R248.1 U6.G19(DCAN1_RX)
SODIMM__UART10_RXD: R174.1 U6.E21(TIMER1)
SODIMM__UART10_TXD: R175.1 U6.F20(TIMER2)
SODIMM_ALT_BOOT: Q7.G(GATE) Q8.G(GATE) R326.1 XP1.185(ALT_BOOT)
SODIMM_BACKUP_BAT: R159.1 R168.1 R319.2 TP27.1 U13.9(VBACKUP)
SODIMM_CLKOUT2/GPIO6_17: R209.2 XP1.152(VIN1A_D0;HDQ0;CLKOUT2;GPIO6_17;)
SODIMM_COLD_RESET_IN: R4.1 U1.3(M\R\) XP1.171(COLD_RESET_IN)
SODIMM_DEBUG_UART3_RXD: R240.2 XP1.117(UART3_RXD;GPIO5_18;SPI3_SCLK;UA)
SODIMM_DEBUG_UART3_TXD: R241.2 XP1.111(UART3_TXD;GPIO5_19;SPI3_D1;SPI4)
SODIMM_DEC_POWER_DOWN: U6.T1(GPIO2_19) XP1.81(GPIO2_4;SPI4_CS3;VIN1A_VSYNC0;V)
SODIMM_EEPROM_WP/QSPI_FLASH_WP: R189.2 R234.1 XP1.189(FLASH_WPN)
SODIMM_ENABLE1(PMIC): U3.J5(ENABLE1) XP1.198(ENABLE1)
SODIMM_ETH0_LED1_LINK_ACT_100/C: R273.2 U17.36(LED1/CFG_LDO0) XP1.97(ETH0_LED_LINK10_100;VIN4A_DE0;V)
SODIMM_ETH0_LED2_LINK_ACT_1000/: R274.2 U17.37(LED2/CFG_LDO1) XP1.109(ETH0_LED_LINK1000)
SODIMM_ETH0_MDI0_N: U17.3(MDIN0) XP1.83(ETH0_MDI0N;VIN4A_D6;VIN1A_D22;V)
SODIMM_ETH0_MDI0_P: U17.2(MDIP0) XP1.85(ETH0_MDI0P;GPIO1_29;VIN4A_D7;VI)
SODIMM_ETH0_MDI1_N: U17.6(MDIN1) XP1.77(ETH0_MDI1N;VIN4A_D4;VIN1A_D20;V)
SODIMM_ETH0_MDI1_P: U17.5(MDIP1) XP1.79(ETH0_MDI1P;VIN4A_D5;VIN1A_D21;V)
SODIMM_ETH0_MDI2_N: U17.8(MDIN2) XP1.89(ETH0_MDI2N;VIN4A_D2;VIN1A_D18;V)
SODIMM_ETH0_MDI2_P: U17.7(MDIP2) XP1.91(ETH0_MDI2P;VIN4A_D3;VIN1A_D19;V)
SODIMM_ETH0_MDI3_N: U17.11(MDIN3) XP1.101(ETH0_MDI3N;VIN4A_D0;VIN1A_D0;VI)
SODIMM_ETH0_MDI3_P: U17.10(MDIP3) XP1.103(ETH0_MDI3P;VIN4A_D1;VIN1A_D17;V)
SODIMM_ETH1_LED1_LINK_ACT_100/C: R302.2 U19.36(LED1/CFG_LDO0) XP1.22(ETH1_LED_LINK10_100)
SODIMM_ETH1_LED2_LINK_ACT_1000/: R303.2 U19.37(LED2/CFG_LDO1) XP1.16(ETH1_LED_LINK1000)
SODIMM_ETH1_MDI0_N: U19.3(MDIN0) XP1.6(ETH1_MDI0N)
SODIMM_ETH1_MDI0_P: U19.2(MDIP0) XP1.8(ETH1_MDI0P)
SODIMM_ETH1_MDI1_N: U19.6(MDIN1) XP1.12(ETH1_MDI1N)
SODIMM_ETH1_MDI1_P: U19.5(MDIP1) XP1.14(ETH1_MDI1P)
SODIMM_ETH1_MDI2_N: U19.8(MDIN2) XP1.18(ETH1_MDI2N)
SODIMM_ETH1_MDI2_P: U19.7(MDIP2) XP1.20(ETH1_MDI2P)
SODIMM_ETH1_MDI3_N: U19.11(MDIN3) XP1.24(ETH1_MDI3N)
SODIMM_ETH1_MDI3_P: U19.10(MDIP3) XP1.26(ETH1_MDI3P)
SODIMM_GPIO1_16: U6.D27(GPIO1_16) XP1.151(GPIO1_16;MMC4_DAT2;UART1_DTRN;U)
SODIMM_GPIO1_17: U6.C28(GPIO1_17) XP1.149(GPIO1_17;MMC4_DAT3;UART1_RIN;UA)
SODIMM_GPIO2_2: U6.P4(GPIO2_2) XP1.95(VIN4A_CLK0;VIN1A_CLK0;VIN2A_CLK)
SODIMM_GPIO3_29/AVID: U6.G2(GPIO3_29) XP1.93(GPIO3_29;VIN2B_FLD1)
SODIMM_GPIO4_0/DEC_INTREQ: U6.G6(PR1_UART0_RTSN) XP1.73(GPIO4_0;SPI4_D1;UART9_TXD;VIN2B)
SODIMM_GPIO5_4: U6.G13(GPIO5_4) XP1.162(HUB_USB_OCN)
SODIMM_GPIO6_16/CLKOUT1: R322.2 XP1.99(VIN4A_FLD0;VIN1A_FLD0;VIN2A_FLD)
SODIMM_GPIO6_18: U6.E17(GPIO6_18) XP1.154(VIN1A_CLK0;MCASP2_AHCLKX;GPIO6_)
SODIMM_GPIO6_19: R173.2 XP1.193(MICIN;MCASP3_AHCLKX;GPIO6_19;TI)
SODIMM_HDMI1_CEC: U6.B20(HDMI_CEC) XP1.34(HDMI1_CEC;DCAN2_RX;GPIO7_13;MMC)
SODIMM_HDMI1_CLOCK_N: U6.AG16(HDMI1_CLOCKX) XP1.32(HDMI1_CLOCKY)
SODIMM_HDMI1_CLOCK_P: U6.AH16(HDMI1_CLOCKY) XP1.30(HDMI1_CLOCKX)
SODIMM_HDMI1_DATA0_N: U6.AG17(HDMI1_DATA0X) XP1.38(HDMI1_DATA0Y)
SODIMM_HDMI1_DATA0_P: U6.AH17(HDMI1_DATA0Y) XP1.36(HDMI1_DATA0X)
SODIMM_HDMI1_DATA1_N: U6.AG18(HDMI1_DATA1X) XP1.44(HDMI1_DATA1Y)
SODIMM_HDMI1_DATA1_P: U6.AH18(HDMI1_DATA1Y) XP1.42(HDMI1_DATA1X)
SODIMM_HDMI1_DATA2_N: U6.AG19(HDMI1_DATA2X) XP1.50(HDMI1_DATA2Y)
SODIMM_HDMI1_DATA2_P: U6.AH19(HDMI1_DATA2Y) XP1.48(HDMI1_DATA2X)
SODIMM_HDMI1_DDC_SCL: U6.C25(HDMI1_DDC_SCL) XP1.25(HDMI1_DDC_SCL;I2C2_SCL)
SODIMM_HDMI1_DDC_SDA: U6.F17(HDMI1_DDC_SDA) XP1.31(HDMI1_DDC_SDA;I2C2_SDA)
SODIMM_HDMI1_HPD: U6.B21(HDMI_HPD) XP1.40(HDMI1_HPD;DCAN2_TX;GPIO7_12;MMC)
SODIMM_I2C5_SCL/UART6_TXD: R242.2 XP1.129(I2C5_SCL;UART6_TXD;GPIO5_3;VIN1)
SODIMM_I2C5_SDA/UART6_RXD: R243.2 XP1.135(I2C5_SDA;UART6_RXD;GPIO5_2;VIN1)
SODIMM_LDOUSB_IN: R50.1 TP16.1 XP1.196(LDOUSB_IN2)
SODIMM_MCASP2_ACLKX: U6.A19(MCASP2_ACLKX) XP1.137(MCASP2_ACLKX;VIN1A_D7;PR2_PRU0_)
SODIMM_MCASP2_AXR0: U6.B15(MCASP2_AXR0) XP1.139(MCASP2_AXR0;VIN4A_D10;VIN1A_D10)
SODIMM_MCASP2_AXR1: U6.A15(MCASP2_AXR1) XP1.143(MCASP2_AXR1;VIN4A_D11;VIN1A_D11)
SODIMM_MCASP2_FSX: U6.A18(MCASP2_FSX) XP1.145(MCASP2_FSX;VIN1A_D6;PR2_PRU0_GP)
SODIMM_MICROSD_MMC1_CLK: U6.W6(MMC1_CLK) XP1.80(MMC1_CLK;GPIO6_21)
SODIMM_MICROSD_MMC1_CMD: U6.Y6(MMC1_CMD) XP1.82(MMC1_CMD;GPIO6_22)
SODIMM_MICROSD_MMC1_DAT0: U6.AA6(MMC1_DAT0) XP1.84(MMC1_DAT0;GPIO6_23)
SODIMM_MICROSD_MMC1_DAT1: U6.Y4(MMC1_DAT1) XP1.86(MMC1_DAT1;GPIO6_24)
SODIMM_MICROSD_MMC1_DAT2: U6.AA5(MMC1_DAT2) XP1.88(MMC1_DAT2;GPIO6_25)
SODIMM_MICROSD_MMC1_DAT3: U6.Y3(MMC1_DAT3) XP1.90(MMC1_DAT3;GPIO6_26)
SODIMM_MICROSD_MMC1_SDCD: U6.W7(MMC1_SDCD) XP1.61(MMC1_SDCD;GPIO6_27;UART6_RXD)
SODIMM_MICROSD_MMC1_SDWP: U6.Y9(GPIO6_28) XP1.67(MMC1_SDWP;GPIO6_28;UART6_TXD)
SODIMM_PCIE_REF_LJCB_CLK_N: C175.1 XP1.121(LJCB_CLKN)
SODIMM_PCIE_REF_LJCB_CLK_P: C176.1 XP1.119(LJCB_CLKP)
SODIMM_PCIE_RX0_N: U6.AG13(PCIE_RXN0) XP1.133(PCIE_RXN0)
SODIMM_PCIE_RX0_P: U6.AH13(PCIE_RXP0) XP1.131(PCIE_RXP0)
SODIMM_PCIE_RX1_N: U6.AG11(PCIE_RXN1) XP1.167(PCIE_RXN1)
SODIMM_PCIE_RX1_P: U6.AH11(PCIE_RXP1) XP1.169(PCIE_RXP1)
SODIMM_PCIE_TX0_N: C169.2 XP1.127(PCIE_TXN0)
SODIMM_PCIE_TX0_P: C168.2 XP1.125(PCIE_TXP0)
SODIMM_PCIE_TX1_N: C174.2 XP1.173(PCIE_TXN1)
SODIMM_PCIE_TX1_P: C172.2 XP1.175(PCIE_TXP1)
SODIMM_PWRON: C22.1 R27.2 U3.G8(PWRON) XP1.165(PWRON)
SODIMM_SATA1_RX0_N: C171.1 XP1.29(SATA1_RXN0)
SODIMM_SATA1_RX0_P: C173.1 XP1.27(SATA1_RXP0)
SODIMM_SATA1_TX0_N: C167.1 XP1.23(SATA1_TXN0)
SODIMM_SATA1_TX0_P: C170.1 XP1.21(SATA1_TXP0)
SODIMM_SPI1_CS0: R258.2 XP1.72(TS_YN;GPIO7_10;SPI1_CS0)
SODIMM_SPI1_D0: R255.2 XP1.66(TS_XP;GPIO7_9;SPI1_D0)
SODIMM_SPI1_D1: R254.2 XP1.68(TS_XN;GPIO7_8;SPI1_D1)
SODIMM_SPI1_SCLK: R253.2 XP1.70(TS_YP;GPIO7_7;SPI1_SCLK)
SODIMM_UART1_RXD: R250.2 XP1.60(UART1_RXD;GPIO7_22;MMC4_SDCD)
SODIMM_UART1_TXD: R251.2 XP1.62(UART1_TXD;GPIO7_23;MMC4_SDWP)
SODIMM_UART2_RXD: R256.2 XP1.155(GPIO7_26;MMC4_DAT0;UART1_DCDN;U)
SODIMM_UART2_TXD: R257.2 XP1.153(GPIO7_27;MMC4_DAT1;UART1_DSRN;U)
SODIMM_UART5_RXD: R213.2 XP1.201(RHPOUT;MCASP3_AXR0;UART5_RXD;UA)
SODIMM_UART5_TXD: R215.2 XP1.197(VIN5A_FLD0;RLINEIN;MCASP3_AXR1;)
SODIMM_UART7_RXD/GPIO5_13: R211.2 XP1.199(LLINEIN;MCASP3_ACLKX;MCASP3_ACL)
SODIMM_UART7_TXD/GPIO5_14: R210.2 XP1.203(LHPOUT;MCASP3_FSX;MCASP3_FSR;GP)
SODIMM_UART8_RXD: R249.2 XP1.54(GPIO1_14;DCAN1_TX;UART8_RXD;HDM)
SODIMM_UART8_TXD: R248.2 XP1.56(SATA1_LED;DCAN1_RX;GPIO1_15;UAR)
SODIMM_UART9_RXD: U6.E25(GPIO7_24) XP1.157(UART9_RXD;GPIO7_24;MMC4_CLK;UAR)
SODIMM_UART9_TXD: U6.C27(GPIO7_25) XP1.147(UART9_TXD;GPIO7_25;MMC4_CMD;UAR)
SODIMM_UART10_RXD: R174.2 XP1.115(UART10_RXD;VIN4A_HSYNC0;VIN1A_H)
SODIMM_UART10_TXD: R175.2 XP1.113(UART10_TXD;VIN4A_VSYNC0;VIN1A_V)
SODIMM_USB1_D_N: U6.AC12(USB1_DM) XP1.178(USB1_DM)
SODIMM_USB1_D_P: U6.AD12(USB1_DP) XP1.176(USB1_DP)
SODIMM_USB1_DRVVBUS: R320.1 U6.AB10(USB1_DRVVBUS)
SODIMM_USB1_ID: U6.B24(GPIO7_17) XP1.174(TBD1)
SODIMM_USB1_RX0_N: U6.AF12(USB_RXN0) XP1.184(USB_RXN0;PCIE_RXN1(AM5718 ONLY))
SODIMM_USB1_RX0_P: U6.AE12(USB_RXP0) XP1.182(USB_RXP0;PCIE_RXP1(AM5718 ONLY))
SODIMM_USB1_TX0_N: C166.2 XP1.190(USB_TXN0;PCIE_TXN1(AM5718 ONLY))
SODIMM_USB1_TX0_P: C165.2 XP1.188(USB_TXP0;PCIE_TXP1(AM5718 ONLY))
SODIMM_USB2_D_N: U6.AF11(USB2_DM) XP1.170(USB2_DM;HUBUSB1_DN)
SODIMM_USB2_D_P: U6.AE11(USB2_DP) XP1.172(USB2_DP;HUBUSB1_DP)
SODIMM_USB2_DRVVBUS: U6.AC10(USB2_DRVVBUS) XP1.156(USB2_DRVVBUS;HUB_USB_PWREN;GPIO)
SODIMM_USB_VBUS: R47.2(P2) TP12.1 XP1.180(VBUS)
SODIMM_VIN4A_CLK0: U6.B11(GPIO4_21) XP1.161(VIN4A_CLK0;VOUT1_FLD;GPIO4_21;S)
SODIMM_VIN4A_D0: U6.B7(VOUT1_D16) XP1.94(VIN4A_D0;VOUT1_D16;GPIO8_16;UAR)
SODIMM_VIN4A_D1: U6.B8(VOUT1_D17) XP1.92(VIN4A_D1;VOUT1_D17;GPIO8_17;UAR)
SODIMM_VIN4A_D2: U6.A7(VOUT1_D18) XP1.142(VIN4A_D2;VOUT1_D18;GPIO8_18;VIN)
SODIMM_VIN4A_D3: U6.A8(VOUT1_D19) XP1.144(VIN4A_D3;VOUT1_D19;GPIO8_19;VIN)
SODIMM_VIN4A_D4: U6.C9(VOUT1_D20) XP1.146(VIN4A_D4;VOUT1_D20;GPIO8_20;VIN)
SODIMM_VIN4A_D5: U6.A9(VOUT1_D21) XP1.148(VIN4A_D5;VOUT1_D21;GPIO8_21;VIN)
SODIMM_VIN4A_D6: U6.B9(VOUT1_D22) XP1.74(VIN4A_D6;VOUT1_D22;GPIO8_22;VIN)
SODIMM_VIN4A_D7: U6.A10(VOUT1_D23) XP1.76(VIN4A_D7;VOUT1_D23;GPIO8_23;SPI)
SODIMM_VIN4A_D8: U6.E8(VOUT1_D8) XP1.124(VIN4A_D8;VOUT1_D8;GPIO8_8;UART6)
SODIMM_VIN4A_D9: U6.D9(VOUT1_D9) XP1.126(VIN4A_D9;VOUT1_D9;GPIO8_9;UART6)
SODIMM_VIN4A_D10: U6.D7(VOUT1_D10) XP1.128(VIN4A_D10;VOUT1_D10;GPIO8_10;VI)
SODIMM_VIN4A_D11: U6.D8(VOUT1_D11) XP1.130(VIN4A_D11;VOUT1_D11;GPIO8_11;VI)
SODIMM_VIN4A_D12: U6.A5(VOUT1_D12) XP1.134(VIN4A_D12;VOUT1_D12;GPIO8_12;VI)
SODIMM_VIN4A_D13: U6.C6(VOUT1_D13) XP1.136(VIN4A_D13;VOUT1_D13;GPIO8_13;VI)
SODIMM_VIN4A_D14: U6.C8(VOUT1_D14) XP1.138(VIN4A_D14;VOUT1_D14;GPIO8_14;VI)
SODIMM_VIN4A_D15: U6.C7(VOUT1_D15) XP1.140(VIN4A_D15;VOUT1_D15;GPIO8_15;VI)
SODIMM_VIN4A_D16: U6.F11(VOUT1_D0) XP1.106(VIN4A_D16;VOUT1_D0;GPIO8_0;SPI3)
SODIMM_VIN4A_D17: U6.G10(VOUT1_D1) XP1.108(VIN4A_D17;VOUT1_D1;GPIO8_1;UART)
SODIMM_VIN4A_D18: U6.F10(VOUT1_D2) XP1.110(VIN4A_D18;VOUT1_D2;GPIO8_2;VIN3)
SODIMM_VIN4A_D19: U6.G11(VOUT1_D3) XP1.112(VIN4A_D19;VOUT1_D3;GPIO8_3;VIN3)
SODIMM_VIN4A_D20: U6.E9(VOUT1_D4) XP1.116(VIN4A_D20;VOUT1_D4;GPIO8_4;VIN3)
SODIMM_VIN4A_D21: U6.F9(VOUT1_D5) XP1.118(VIN4A_D21;VOUT1_D5;GPIO8_5;VIN3)
SODIMM_VIN4A_D22: U6.F8(VOUT1_D6) XP1.120(VIN4A_D22;VOUT1_D6;GPIO8_6;VIN3)
SODIMM_VIN4A_D23: U6.E7(VOUT1_D7) XP1.122(VIN4A_D23;VOUT1_D7;GPIO8_7;VIN3)
SODIMM_VIN4A_DE0: U6.B10(VOUT1_DE) XP1.104(VIN4A_DE0;VOUT1_DE;GPIO4_20;SPI)
SODIMM_VIN4A_FLD0: U6.D11(VOUT1_CLK) XP1.98(VIN4A_FLD0;VOUT1_CLK;GPIO4_19;S)
SODIMM_VIN4A_HSYNC0: U6.C11(VOUT1_HSYNC) XP1.100(VIN4A_HSYNC0;VOUT1_HSYNC;GPIO4_)
SODIMM_VIN4A_VSYNC0: U6.E11(VOUT1_VSYNC) XP1.102(VIN4A_VSYNC0;VOUT1_VSYNC;GPIO4_)
SODIMM_VIN5A_D8: U6.AA4(UART9_RTSN) XP1.9(VIN5A_D8;MCASP5_AXR1;SPI4_CS0;U)
SODIMM_VIN5A_D9: U6.AB3(UART9_CTSN) XP1.7(VIN5A_D9;MCASP5_AXR0;SPI4_D0;UA)
SODIMM_VIN5A_D10: U6.AB9(UART9_TXD) XP1.3(VIN5A_D10;I2C5_SCL;MCASP5_FSR;M)
SODIMM_VIN5A_D11: U6.AA3(UART9_RXD) XP1.5(VIN5A_D11;I2C5_SDA;MCASP5_ACLKR)
SODIMM_VIN5A_D12: U6.D17(UART8_RTSN) XP1.17(VIN5A_D12;MCASP4_AXR1;SPI3_CS0;)
SODIMM_VIN5A_D13: U6.G16(UART8_CTSN) XP1.15(VIN5A_D13;MCASP4_AXR0;SPI3_D0;U)
SODIMM_VIN5A_D14: U6.A21(UART8_TXD) XP1.11(VIN5A_D14;MCASP4_FSR;MCASP4_FSX)
SODIMM_VIN5A_D15: U6.C18(UART8_RXD) XP1.13(VIN5A_D15;MCASP4_ACLKR;MCASP4_A)
SODIMM_WAKEUP1/GPIO1_1: R59.1 U6.AC17(WAKEUP1) XP1.192(WAKEUP1;GPIO1_1)
SODIMM_WARM_RESETN: C55.1 R54.2 U5.1(A) XP1.187(RESETN)
SYS_WARMRESETN: C59.1 R55.1 U5.4(Y) U6.E23(RESETN)
SYSBOOT0: R224.2(P2) R225.1 U6.M6(VIN3A_D0)
SYSBOOT1: R222.2(P2) R223.1 U6.M2(VIN3A_D1)
SYSBOOT2: R220.2(P2) R221.1 U6.L5(VIN3A_D2)
SYSBOOT3: R218.2(P2) R219.1 U6.M1(VIN3A_D3)
SYSBOOT4: R216.2(P2) R217.1 R329.2(P2) U6.L6(VIN3A_D4)
SYSBOOT5: R212.2(P2) R214.1 R324.2(P2) U6.L4(VIN3A_D5)
SYSBOOT6: R207.2(P2) R208.1 U6.L3(VIN3A_D6)
SYSBOOT7: R205.2(P2) R206.1 U6.L2(VIN3A_D7)
SYSBOOT8: R203.2(P2) R204.1 U6.L1(VIN3A_D8)
SYSBOOT9: R201.2(P2) R202.1 U6.K2(VIN3A_D9)
SYSBOOT10: R199.2(P2) R200.1 U6.J1(VIN3A_D10)
SYSBOOT11: R197.2(P2) R198.1 U6.J2(VIN3A_D11)
SYSBOOT12: R194.2(P2) R196.1 U6.H1(VIN3A_D12)
SYSBOOT13: R190.2(P2) R191.1 U6.J3(VIN3A_D13)
SYSBOOT14: R184.1 R185.2(P2) U6.H2(VIN3A_D14)
SYSBOOT15: R182.2(P2) R183.1 U6.H3(VIN3A_D15)
TCK: R155.2 R171.1 U6.E20(TCLK)
TCLK: P1.11(TCLK) R171.2
TDI: P1.3(TDI) U6.D23(TDI)
TDO: P1.7(TDO) R166.2
TDOR: R166.1 U6.F19(TDO)
TMS: P1.1(TMS) R156.2 U6.F18(TMS)
TRSTN: P1.2(TRSTN) R158.1 U6.D20(TRSTN)
USB1_TX0_N: C166.1 U6.AC11(USB_TXN0)
USB1_TX0_P: C165.1 U6.AD11(USB_TXP0)
USER_LED_BLUE: Q6.G(GATE) R239.2 U6.D12(GPIO5_9)
USER_LED_GREEN: Q4.G(GATE) R237.2 U6.F13(GPIO5_7)
USER_LED_RED: Q5.G(GATE) R238.2 U6.C12(GPIO5_8)
VREF_DDR: C12.1 C74.2 C75.2 C76.1 C77.1 C78.1 C79.1 C102.1 C111.2 C112.2 C113.1 C114.1 C115.1 C116.1 C139.2 TP3.1 U2.6(VRO) U6.N22(DDR2_VREF0) U6.Y18(DDR1_VREF0) U8.H1(VREFDQ) U8.M8(VREFCA) U9.H1(VREFDQ) U9.M8(VREFCA) U10.H1(VREFDQ) U10.M8(VREFCA) U11.H1(VREFDQ) U11.M8(VREFCA)
